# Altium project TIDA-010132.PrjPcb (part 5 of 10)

## Sheet CLOCK MAIN SHEET.SchDoc
size 558 x 431 mm; Date: Not shown in title block; ApprovedBy: Not shown in title block; CheckedBy: Not shown in title block; Author: Not shown in title block; CompanyName: Not shown in title block; DrawnBy: Avinash N; Engineer: Not shown in title block; Organization: Not shown in title block; Address1: Not shown in title block; Address2: Not shown in title block; Address3: Not shown in title block; Address4: Not shown in title block; DocumentNumber: 1; Revision: Use project parameter SCH_Rev; SheetNumber: 24; SheetTotal: 32; PageSetup: Record=PageOptions¦CenterHorizontal=True¦CenterVertical=True¦PrintScale=1.00¦XCorrection=1.00¦YCorrection=1.00¦PrintKind=0¦BorderSize=5000000¦LeftOffset=0¦BottomOffset=0¦Orientation=2¦PaperLength=1000¦PaperWidth=1000¦Scale=100¦PaperSource=15¦PrintQuality=600¦MediaType=1¦DitherType=10¦PaperKind=Letter¦PrintScaleMode=1
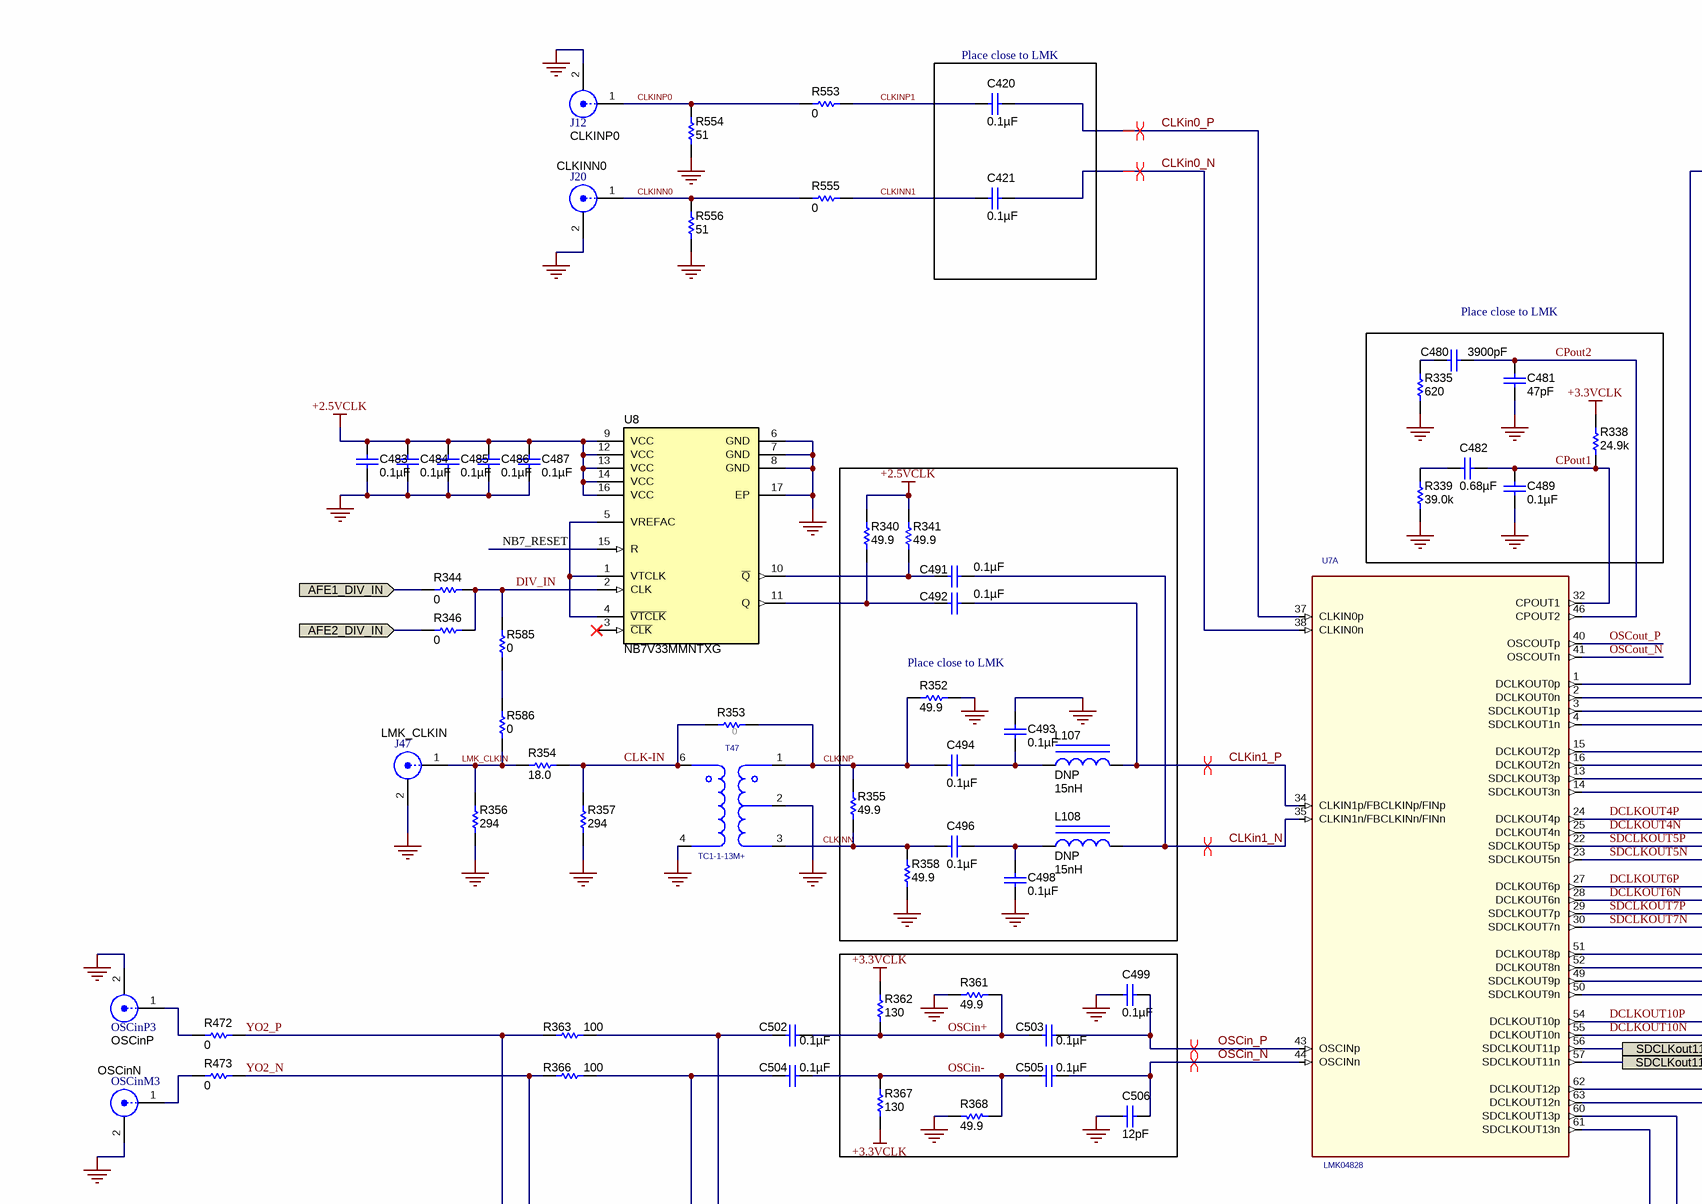
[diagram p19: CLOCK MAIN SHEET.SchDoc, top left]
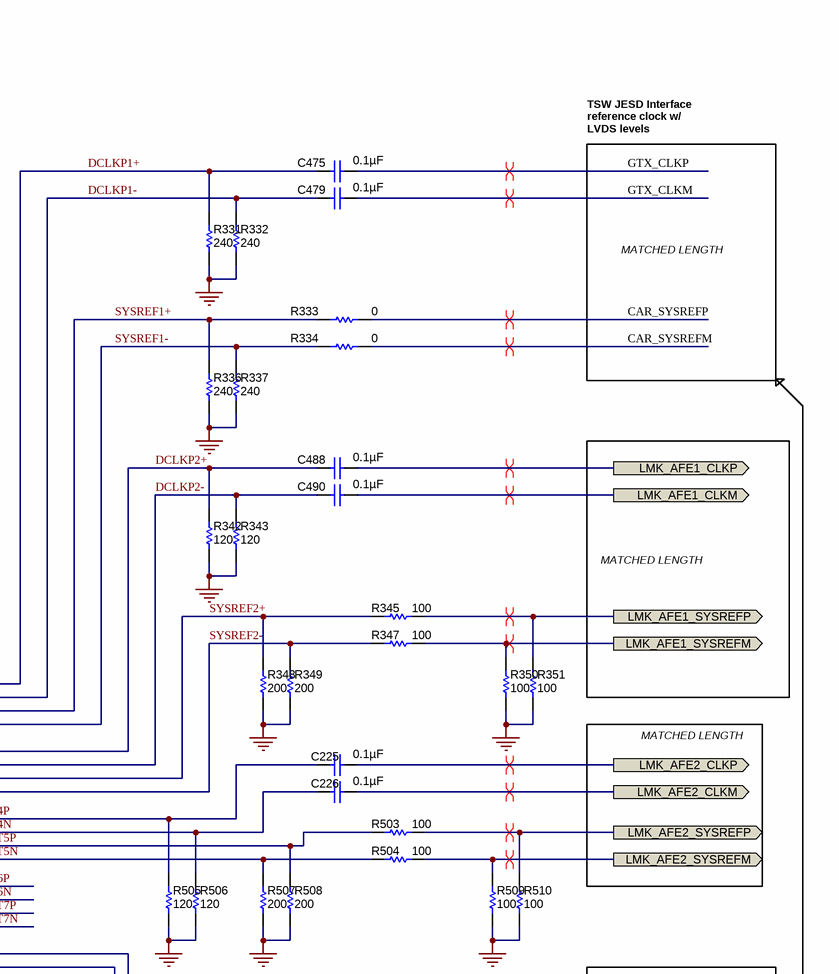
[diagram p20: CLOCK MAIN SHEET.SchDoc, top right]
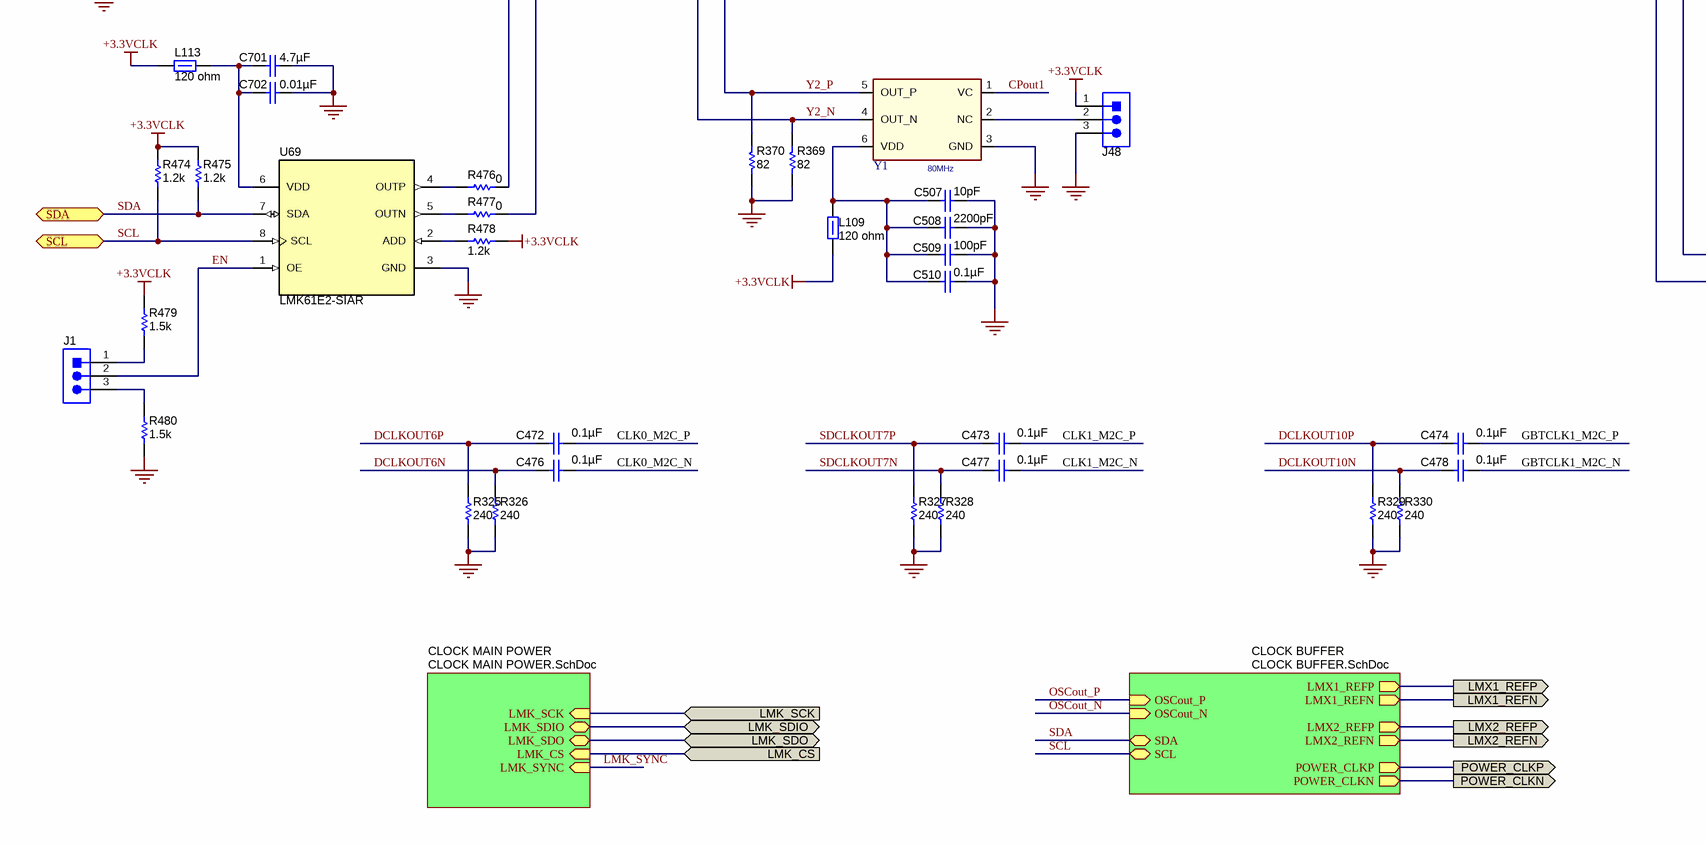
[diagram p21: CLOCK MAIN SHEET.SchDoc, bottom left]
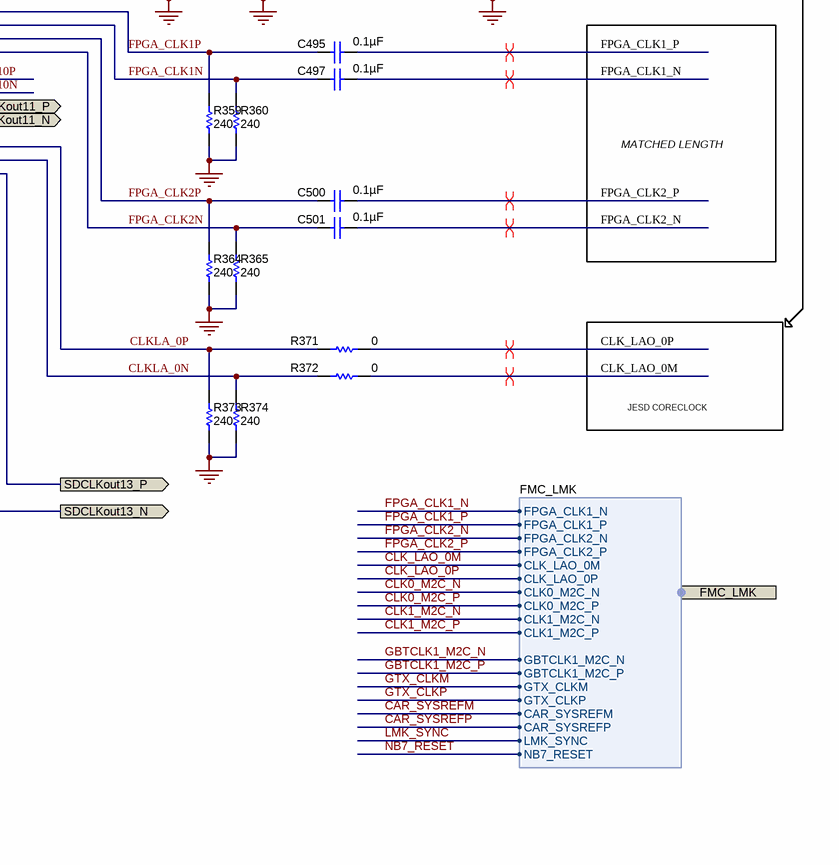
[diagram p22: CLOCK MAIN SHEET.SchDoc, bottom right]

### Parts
C225  ValueDisplayed: 0.1µF  [0402]  (hidden comment: C1005X7R1E104M050BB)
C226  ValueDisplayed: 0.1µF  [0402]  (hidden comment: C1005X7R1E104M050BB)
C420  ValueDisplayed: 0.1µF  [0201_033]  (hidden comment: GRM033R60J104KE19D)
C421  ValueDisplayed: 0.1µF  [0201_033]  (hidden comment: GRM033R60J104KE19D)
C472  ValueDisplayed: 0.1µF  [0402]  (hidden comment: C1005X7R1E104M050BB)
C473  ValueDisplayed: 0.1µF  [0402]  (hidden comment: C1005X7R1E104M050BB)
C474  ValueDisplayed: 0.1µF  [0402]  (hidden comment: C1005X7R1E104M050BB)
C475  ValueDisplayed: 0.1µF  [0402]  (hidden comment: C1005X7R1E104M050BB)
C476  ValueDisplayed: 0.1µF  [0402]  (hidden comment: C1005X7R1E104M050BB)
C477  ValueDisplayed: 0.1µF  [0402]  (hidden comment: C1005X7R1E104M050BB)
C478  ValueDisplayed: 0.1µF  [0402]  (hidden comment: C1005X7R1E104M050BB)
C479  ValueDisplayed: 0.1µF  [0402]  (hidden comment: C1005X7R1E104M050BB)
C480  ValueDisplayed: 3900pF  [0201]  (hidden comment: 0201ZD392KAT2A)
C481  ValueDisplayed: 47pF  [0201_033]  (hidden comment: GRM0335C1E470JA01D)
C482  ValueDisplayed: 0.68µF  [0402]  (hidden comment: C1005X5R1A684K050BB)
C483  ValueDisplayed: 0.1µF  [0402]  (hidden comment: C1005X7R1E104M050BB)
C484  ValueDisplayed: 0.1µF  [0402]  (hidden comment: C1005X7R1E104M050BB)
C485  ValueDisplayed: 0.1µF  [0402]  (hidden comment: C1005X7R1E104M050BB)
C486  ValueDisplayed: 0.1µF  [0402]  (hidden comment: C1005X7R1E104M050BB)
C487  ValueDisplayed: 0.1µF  [0402]  (hidden comment: C1005X7R1E104M050BB)
C488  ValueDisplayed: 0.1µF  [0402]  (hidden comment: C1005X7R1E104M050BB)
C489  ValueDisplayed: 0.1µF  [0402]  (hidden comment: C1005X7R1E104M050BB)
C490  ValueDisplayed: 0.1µF  [0402]  (hidden comment: C1005X7R1E104M050BB)
C491  ValueDisplayed: 0.1µF  [0201_033]  (hidden comment: GRM033R60J104KE19D)
C492  ValueDisplayed: 0.1µF  [0201_033]  (hidden comment: GRM033R60J104KE19D)
C493  ValueDisplayed: 0.1µF  [0201_033]  (hidden comment: GRM033R60J104KE19D)
C494  ValueDisplayed: 0.1µF  [0201_033]  (hidden comment: GRM033R60J104KE19D)
C495  ValueDisplayed: 0.1µF  [0402]  (hidden comment: C1005X7R1E104M050BB)
C496  ValueDisplayed: 0.1µF  [0201_033]  (hidden comment: GRM033R60J104KE19D)
C497  ValueDisplayed: 0.1µF  [0402]  (hidden comment: C1005X7R1E104M050BB)
C498  ValueDisplayed: 0.1µF  [0201_033]  (hidden comment: GRM033R60J104KE19D)
C499  ValueDisplayed: 0.1µF  [0402]  (hidden comment: C1005X7R1E104M050BB)
C500  ValueDisplayed: 0.1µF  [0402]  (hidden comment: C1005X7R1E104M050BB)
C501  ValueDisplayed: 0.1µF  [0402]  (hidden comment: C1005X7R1E104M050BB)
C502  ValueDisplayed: 0.1µF  [0402]  (hidden comment: C1005X7R1E104M050BB)
C503  ValueDisplayed: 0.1µF  [0402]  (hidden comment: C1005X7R1E104M050BB)
C504  ValueDisplayed: 0.1µF  [0402]  (hidden comment: C1005X7R1E104M050BB)
C505  ValueDisplayed: 0.1µF  [0402]  (hidden comment: C1005X7R1E104M050BB)
C506  ValueDisplayed: 12pF  [0402]  (hidden comment: C0402C120J3GACAUTO)
C507  ValueDisplayed: 10pF  [0402]  (hidden comment: GRM1555C1H100JA01D)
C508  ValueDisplayed: 2200pF  [0402]  (hidden comment: GRM155R71E222KA01D)
C509  ValueDisplayed: 100pF  [0402]  (hidden comment: 04025A101FAT2A)
C510  ValueDisplayed: 0.1µF  [0402]  (hidden comment: C1005X7R1E104M050BB)
C701  ValueDisplayed: 4.7µF  [0402]  (hidden comment: C1005X5R0J475M050BC)
C702  ValueDisplayed: 0.01µF  [0402]  (hidden comment: GRM155R71E103KA01D)
J1  800-10-003-10-001000  [Mill-Max_800-10-003-10-001000]  (value not drawn)
J12  CLKINP0  [Molex_0853050232]
J20  CLKINN0  [Molex_0853050232]
J47  LMK_CLKIN  [Molex_0853050232]
J48  0022284033  [Molex_0022284033]  (value not drawn)
L107  DNP  ValueDisplayed: 15nH  [IND_LQG15H]
L108  DNP  ValueDisplayed: 15nH  [IND_LQG15H]
L109  ValueDisplayed: 120 ohm  [0603]  (hidden comment: BLM18SG121TN1D)
L113  ValueDisplayed: 120 ohm  [0603]  (hidden comment: BLM18SG121TN1D)
OSCinM3  OSCinN  [Molex_0853050232]
OSCinP3  OSCinP  [Molex_0853050232]
R325  ValueDisplayed: 240  [0402]  (hidden comment: ERJ-2RKF2400X)
R326  ValueDisplayed: 240  [0402]  (hidden comment: ERJ-2RKF2400X)
R327  ValueDisplayed: 240  [0402]  (hidden comment: ERJ-2RKF2400X)
R328  ValueDisplayed: 240  [0402]  (hidden comment: ERJ-2RKF2400X)
R329  ValueDisplayed: 240  [0402]  (hidden comment: ERJ-2RKF2400X)
R330  ValueDisplayed: 240  [0402]  (hidden comment: ERJ-2RKF2400X)
R331  ValueDisplayed: 240  [0402]  (hidden comment: ERJ-2RKF2400X)
R332  ValueDisplayed: 240  [0402]  (hidden comment: ERJ-2RKF2400X)
R333  ValueDisplayed: 0  [0402]  (hidden comment: ERJ-2GE0R00X)
R334  ValueDisplayed: 0  [0402]  (hidden comment: ERJ-2GE0R00X)
R335  ValueDisplayed: 620  [0201]  (hidden comment: RC0201FR-07620RL)
R336  ValueDisplayed: 240  [0402]  (hidden comment: ERJ-2RKF2400X)
R337  ValueDisplayed: 240  [0402]  (hidden comment: ERJ-2RKF2400X)
R338  ValueDisplayed: 24.9k  [0603]  (hidden comment: CRCW060324K9FKEA)
R339  ValueDisplayed: 39.0k  [0201]  (hidden comment: RC0201FR-0739KL)
R340  ValueDisplayed: 49.9  [0201]  (hidden comment: CRCW020149R9FKED)
R341  ValueDisplayed: 49.9  [0201]  (hidden comment: CRCW020149R9FKED)
R342  ValueDisplayed: 120  [0402]  (hidden comment: CRCW0402120RJNED)
R343  ValueDisplayed: 120  [0402]  (hidden comment: CRCW0402120RJNED)
R344  ValueDisplayed: 0  [0402]  (hidden comment: CRCW04020000Z0ED)
R345  ValueDisplayed: 100  [0402]  (hidden comment: ERJ-2RKF1000X)
R346  ValueDisplayed: 0  [0402]  (hidden comment: CRCW04020000Z0ED)
R347  ValueDisplayed: 100  [0402]  (hidden comment: ERJ-2RKF1000X)
R348  ValueDisplayed: 200  [0402]  (hidden comment: CRCW0402200RJNED)
R349  ValueDisplayed: 200  [0402]  (hidden comment: CRCW0402200RJNED)
R350  ValueDisplayed: 100  [0402]  (hidden comment: ERJ-2RKF1000X)
R351  ValueDisplayed: 100  [0402]  (hidden comment: ERJ-2RKF1000X)
R352  ValueDisplayed: 49.9  [0201]  (hidden comment: CRCW020149R9FKED)
R353  ValueDisplayed: 0  [0603]  (hidden comment: CRCW06030000Z0EA)
R354  ValueDisplayed: 18.0  [0603]  (hidden comment: RC0603FR-0718RL)
R355  ValueDisplayed: 49.9  [0201]  (hidden comment: CRCW020149R9FKED)
R356  ValueDisplayed: 294  [0603]  (hidden comment: CRCW0603294RFKEA)
R357  ValueDisplayed: 294  [0603]  (hidden comment: CRCW0603294RFKEA)
R358  ValueDisplayed: 49.9  [0201]  (hidden comment: CRCW020149R9FKED)
R359  ValueDisplayed: 240  [0402]  (hidden comment: ERJ-2RKF2400X)
R360  ValueDisplayed: 240  [0402]  (hidden comment: ERJ-2RKF2400X)
R361  ValueDisplayed: 49.9  [0402]  (hidden comment: CRCW040249R9FKED)
R362  ValueDisplayed: 130  [0402]  (hidden comment: CRCW0402130RFKED)
R363  ValueDisplayed: 100  [0402]  (hidden comment: ERJ-2RKF1000X)
R364  ValueDisplayed: 240  [0402]  (hidden comment: ERJ-2RKF2400X)
R365  ValueDisplayed: 240  [0402]  (hidden comment: ERJ-2RKF2400X)
R366  ValueDisplayed: 100  [0402]  (hidden comment: ERJ-2RKF1000X)
R367  ValueDisplayed: 130  [0402]  (hidden comment: CRCW0402130RFKED)
R368  ValueDisplayed: 49.9  [0402]  (hidden comment: CRCW040249R9FKED)
R369  ValueDisplayed: 82  [0402]  (hidden comment: CRCW040282R0JNED)
R370  ValueDisplayed: 82  [0402]  (hidden comment: CRCW040282R0JNED)
R371  ValueDisplayed: 0  [0402]  (hidden comment: ERJ-2GE0R00X)
R372  ValueDisplayed: 0  [0402]  (hidden comment: ERJ-2GE0R00X)
R373  ValueDisplayed: 240  [0402]  (hidden comment: ERJ-2RKF2400X)
R374  ValueDisplayed: 240  [0402]  (hidden comment: ERJ-2RKF2400X)
R472  ValueDisplayed: 0  [0402]  (hidden comment: CRCW04020000Z0ED)
R473  ValueDisplayed: 0  [0402]  (hidden comment: CRCW04020000Z0ED)
R474  ValueDisplayed: 1.2k  [0402]  (hidden comment: CRCW04021K20JNED)
R475  ValueDisplayed: 1.2k  [0402]  (hidden comment: CRCW04021K20JNED)
R476  ValueDisplayed: 0  [0402]  (hidden comment: CRCW04020000Z0ED)
R477  ValueDisplayed: 0  [0402]  (hidden comment: CRCW04020000Z0ED)
R478  ValueDisplayed: 1.2k  [0402]  (hidden comment: CRCW04021K20JNED)
R479  ValueDisplayed: 1.5k  [0402]  (hidden comment: CRCW04021K50JNED)
R480  ValueDisplayed: 1.5k  [0402]  (hidden comment: CRCW04021K50JNED)
R503  ValueDisplayed: 100  [0402]  (hidden comment: ERJ-2RKF1000X)
R504  ValueDisplayed: 100  [0402]  (hidden comment: ERJ-2RKF1000X)
R505  ValueDisplayed: 120  [0402]  (hidden comment: CRCW0402120RJNED)
R506  ValueDisplayed: 120  [0402]  (hidden comment: CRCW0402120RJNED)
R507  ValueDisplayed: 200  [0402]  (hidden comment: CRCW0402200RJNED)
R508  ValueDisplayed: 200  [0402]  (hidden comment: CRCW0402200RJNED)
R509  ValueDisplayed: 100  [0402]  (hidden comment: ERJ-2RKF1000X)
R510  ValueDisplayed: 100  [0402]  (hidden comment: ERJ-2RKF1000X)
R553  ValueDisplayed: 0  [0201]  (hidden comment: CRCW02010000Z0ED)
R554  ValueDisplayed: 51  [0201]  (hidden comment: RC0201JR-0751RL)
R555  ValueDisplayed: 0  [0201]  (hidden comment: CRCW02010000Z0ED)
R556  ValueDisplayed: 51  [0201]  (hidden comment: RC0201JR-0751RL)
R585  ValueDisplayed: 0  [0402]  (hidden comment: CRCW04020000Z0ED)
R586  ValueDisplayed: 0  [0402]  (hidden comment: CRCW04020000Z0ED)
T47  TC1-1-13M+  [TFMR_5_150x150_50]
U7  LMK04828  [NKD0064A]  (part A of 2)
U8  NB7V33MMNTXG  [QFN16-3x3MM_0_5]
U69  LMK61E2-SIAR  [SIA0008B]
Y1  80MHz  [VCXO_6_CUSTOM]

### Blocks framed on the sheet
Place close to LMK: C420 C421
Place close to LMK: C480-C482 C489 R335 R338 R339
Place close to LMK: C491-C494 C496 C498 L107 L108 R340 R341 R352 R355 R358

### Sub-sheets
CLOCK BUFFER = CLOCK BUFFER.SchDoc: POWER_CLKP (out), LMX2_REFP (out), POWER_CLKN (out), LMX1_REFP (out), SCL (bidir), SDA (bidir), OSCout_N (in), OSCout_P (in), LMX1_REFN (out), LMX2_REFN (out)
CLOCK MAIN POWER = CLOCK MAIN POWER.SchDoc: LMK_SYNC (in), LMK_SDO (bidir), LMK_CS (in), LMK_SCK (in), LMK_SDIO (bidir)

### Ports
AFE1_DIV_IN (in), AFE2_DIV_IN (in), FMC_LMK (harness FMC_LMK), LMK_AFE1_CLKM (out), LMK_AFE1_CLKP (out), LMK_AFE1_SYSREFM (out), LMK_AFE1_SYSREFP (out), LMK_AFE2_CLKM (out), LMK_AFE2_CLKP (out), LMK_AFE2_SYSREFM (out), LMK_AFE2_SYSREFP (out), LMK_CS (in), LMK_SCK (in), LMK_SDIO (bidir), LMK_SDO (bidir), LMX1_REFN (out), LMX1_REFP (out), LMX2_REFN (out), LMX2_REFP (out), POWER_CLKN (out), POWER_CLKP (out), SCL (bidir), SDA (bidir), SDCLKout11_N (out), SDCLKout11_P (out), SDCLKout13_N (out), SDCLKout13_P (out)

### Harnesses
FMC_LMK: FPGA_CLK1_N, FPGA_CLK1_P, FPGA_CLK2_N, FPGA_CLK2_P, GBTCLK1_M2C_N, GBTCLK1_M2C_P, GTX_CLKM, GTX_CLKP, CAR_SYSREFM, CAR_SYSREFP, LMK_SYNC, NB7_RESET, CLK_LAO_0M, CLK_LAO_0P, CLK0_M2C_N, CLK0_M2C_P, CLK1_M2C_N, CLK1_M2C_P

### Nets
+2.5VCLK: C483.2 C484.2 C485.2 C486.2 C487.2 R340.2 R341.2 U8.9(VCC) U8.12(VCC) U8.13(VCC) U8.14(VCC) U8.16(VCC)
+3.3VCLK: J48.1 L109.2 L113.1 R338.2 R362.1 R367.1 R474.2 R475.2 R478.1 R479.2
GND: C481.2 C483.1 C484.1 C485.1 C486.1 C487.1 C489.1 C493.1 C498.1 C499.1 C506.1 C507.1 C508.1 C509.1 C510.1 C701.1 C702.1 J12.2 J20.2 J47.2 J48.3 OSCinM3.2 OSCinP3.2 R325.1 R326.1 R327.1 R328.1 R329.1 R330.1 R331.1 R332.1 R335.1 R336.1 R337.1 R339.1 R342.1 R343.1 R348.1 R349.1 R350.1 R351.1 R352.2 R356.1 R357.1 R358.1 R359.1 R360.1 R361.1 R364.1 R365.1 R368.1 R369.1 R370.1 R373.1 R374.1 R480.1 R505.1 R506.1 R507.1 R508.1 R509.1 R510.1 R554.1 R556.1 T47.2(secondary_ct) T47.4(primary) U8.6(GND) U8.7(GND) U8.8(GND) U8.17(EP) U69.3(GND) Y1.3(GND)
AFE1_DIV_IN: R344.2 ; port AFE1_DIV_IN
AFE2_DIV_IN: R346.2 ; port AFE2_DIV_IN
CAR_SYSREFM: R334.2 ; port FMC_LMK.CAR_SYSREFM
CAR_SYSREFP: R333.2 ; port FMC_LMK.CAR_SYSREFP
CLK0_M2C_N: C476.2 ; port FMC_LMK.CLK0_M2C_N
CLK0_M2C_P: C472.2 ; port FMC_LMK.CLK0_M2C_P
CLK1_M2C_N: C477.2 ; port FMC_LMK.CLK1_M2C_N
CLK1_M2C_P: C473.2 ; port FMC_LMK.CLK1_M2C_P
CLK-IN: R353.1 R354.2 R357.2 T47.6(primary_dot)
CLK_LAO_0M: R372.2 ; port FMC_LMK.CLK_LAO_0M
CLK_LAO_0P: R371.2 ; port FMC_LMK.CLK_LAO_0P
CLKin0_N: C421.2 U7.38(CLKIN0n)
CLKin0_P: C420.2 U7.37(CLKIN0p)
CLKin1_N: C491.2 L108.2 U7.35(CLKIN1n/FBCLKINn/FINn)
CLKin1_P: C492.2 L107.2 U7.34(CLKIN1p/FBCLKINp/FINp)
CLKINN: C496.1 R355.1 R358.2 T47.3(secondary)
CLKINN0: J20.1 R555.1 R556.2
CLKINN1: C421.1 R555.2
CLKINP: C494.1 R352.1 R353.2 R355.2 T47.1(secondary_dot)
CLKINP0: J12.1 R553.1 R554.2
CLKINP1: C420.1 R553.2
CLKLA_0N: R372.1 R374.2 U7.63(DCLKOUT12n)
CLKLA_0P: R371.1 R373.2 U7.62(DCLKOUT12p)
CPout1: C482.2 C489.2 R338.1 U7.32(CPOUT1) Y1.1(VC)
CPout2: C480.1 C481.1 U7.46(CPOUT2)
DCLKOUT4N: C226.1 R506.2 U7.25(DCLKOUT4n)
DCLKOUT4P: C225.1 R505.2 U7.24(DCLKOUT4p)
DCLKOUT6N: C476.1 R326.2 U7.28(DCLKOUT6n)
DCLKOUT6P: C472.1 R325.2 U7.27(DCLKOUT6p)
DCLKOUT10N: C478.1 R330.2 U7.55(DCLKOUT10n)
DCLKOUT10P: C474.1 R329.2 U7.54(DCLKOUT10p)
DCLKP1+: C475.1 R331.2 U7.1(DCLKOUT0p)
DCLKP1-: C479.1 R332.2 U7.2(DCLKOUT0n)
DCLKP2+: C488.1 R342.2 U7.15(DCLKOUT2p)
DCLKP2-: C490.1 R343.2 U7.16(DCLKOUT2n)
DIV_IN: R344.1 R346.1 R585.1 U8.2(CLK)
EN: J1.2 U69.1(OE)
FPGA_CLK1_N: C497.2 ; port FMC_LMK.FPGA_CLK1_N
FPGA_CLK1_P: C495.2 ; port FMC_LMK.FPGA_CLK1_P
FPGA_CLK1N: C497.1 R360.2 U7.52(DCLKOUT8n)
FPGA_CLK1P: C495.1 R359.2 U7.51(DCLKOUT8p)
FPGA_CLK2_N: C501.2 ; port FMC_LMK.FPGA_CLK2_N
FPGA_CLK2_P: C500.2 ; port FMC_LMK.FPGA_CLK2_P
FPGA_CLK2N: C501.1 R365.2 U7.50(SDCLKOUT9n)
FPGA_CLK2P: C500.1 R364.2 U7.49(SDCLKOUT9p)
GBTCLK1_M2C_N: C478.2 ; port FMC_LMK.GBTCLK1_M2C_N
GBTCLK1_M2C_P: C474.2 ; port FMC_LMK.GBTCLK1_M2C_P
GTX_CLKM: C479.2 ; port FMC_LMK.GTX_CLKM
GTX_CLKP: C475.2 ; port FMC_LMK.GTX_CLKP
LMK_AFE1_CLKM: C490.2 ; port LMK_AFE1_CLKM
LMK_AFE1_CLKP: C488.2 ; port LMK_AFE1_CLKP
LMK_AFE1_SYSREFM: R347.2 R350.2 ; port LMK_AFE1_SYSREFM
LMK_AFE1_SYSREFP: R345.2 R351.2 ; port LMK_AFE1_SYSREFP
LMK_AFE2_CLKM: C226.2 ; port LMK_AFE2_CLKM
LMK_AFE2_CLKP: C225.2 ; port LMK_AFE2_CLKP
LMK_AFE2_SYSREFM: R504.2 R509.2 ; port LMK_AFE2_SYSREFM
LMK_AFE2_SYSREFP: R503.2 R510.2 ; port LMK_AFE2_SYSREFP
LMK_CLKIN: J47.1 R354.1 R356.2 R586.2
LMK_CS: port LMK_CS, sheet CLOCK MAIN POWER/LMK_CS
LMK_SCK: port LMK_SCK, sheet CLOCK MAIN POWER/LMK_SCK
LMK_SDIO: port LMK_SDIO, sheet CLOCK MAIN POWER/LMK_SDIO
LMK_SDO: port LMK_SDO, sheet CLOCK MAIN POWER/LMK_SDO
LMK_SYNC: sheet CLOCK MAIN POWER/LMK_SYNC, port FMC_LMK.LMK_SYNC
LMX1_REFN: port LMX1_REFN, sheet CLOCK BUFFER/LMX1_REFN
LMX1_REFP: port LMX1_REFP, sheet CLOCK BUFFER/LMX1_REFP
LMX2_REFN: port LMX2_REFN, sheet CLOCK BUFFER/LMX2_REFN
LMX2_REFP: port LMX2_REFP, sheet CLOCK BUFFER/LMX2_REFP
NB7_RESET: U8.15(R) ; port FMC_LMK.NB7_RESET
OSCin+: C502.1 C503.2 R361.2 R362.2
OSCin-: C504.1 C505.2 R367.2 R368.2
OSCin_N: C505.1 C506.2 U7.44(OSCINn)
OSCin_P: C499.2 C503.1 U7.43(OSCINp)
OSCout_N: U7.41(OSCOUTn) ; sheet CLOCK BUFFER/OSCout_N
OSCout_P: U7.40(OSCOUTp) ; sheet CLOCK BUFFER/OSCout_P
POWER_CLKN: port POWER_CLKN, sheet CLOCK BUFFER/POWER_CLKN
POWER_CLKP: port POWER_CLKP, sheet CLOCK BUFFER/POWER_CLKP
SCL: R474.1 U69.8(SCL) ; port SCL, sheet CLOCK BUFFER/SCL
SDA: R475.1 U69.7(SDA) ; port SDA, sheet CLOCK BUFFER/SDA
SDCLKOUT5N: R504.1 R507.2 U7.23(SDCLKOUT5n)
SDCLKOUT5P: R503.1 R508.2 U7.22(SDCLKOUT5p)
SDCLKOUT7N: C477.1 R328.2 U7.30(SDCLKOUT7n)
SDCLKOUT7P: C473.1 R327.2 U7.29(SDCLKOUT7p)
SDCLKout11_N: U7.57(SDCLKOUT11n) ; port SDCLKout11_N
SDCLKout11_P: U7.56(SDCLKOUT11p) ; port SDCLKout11_P
SDCLKout13_N: U7.61(SDCLKOUT13n) ; port SDCLKout13_N
SDCLKout13_P: U7.60(SDCLKOUT13p) ; port SDCLKout13_P
SYSREF1+: R333.1 R336.2 U7.3(SDCLKOUT1p)
SYSREF1-: R334.1 R337.2 U7.4(SDCLKOUT1n)
SYSREF2+: R345.1 R348.2 U7.13(SDCLKOUT3p)
SYSREF2-: R347.1 R349.2 U7.14(SDCLKOUT3n)
Y2_N: C504.2 R366.2 R369.2 Y1.4(OUT_N)
Y2_P: C502.2 R363.2 R370.2 Y1.5(OUT_P)
YO2_N: R366.1 R473.1 R477.2
YO2_P: R363.1 R472.1 R476.2
NetC480_2: C480.2 R335.2
NetC482_1: C482.1 R339.2
NetC491_1: C491.1 R341.1 U8.10(~{Q})
NetC492_1: C492.1 R340.1 U8.11(Q)
NetC493_2: C493.2 C494.2 L107.1
NetC496_2: C496.2 C498.2 L108.1
NetC507_2: C507.2 C508.2 C509.2 C510.2 L109.1 Y1.6(VDD)
NetC701_2: C701.2 C702.2 L113.2 U69.6(VDD)
NetJ1_1: J1.1 R479.1
NetJ1_3: J1.3 R480.2
NetJ48_2: J48.2 Y1.2(NC)
NetOSCinM3_1: OSCinM3.1 R473.2
NetOSCinP3_1: OSCinP3.1 R472.2
NetR476_1: R476.1 U69.4(OUTP)
NetR477_1: R477.1 U69.5(OUTN)
NetR478_2: R478.2 U69.2(ADD)
NetR585_2: R585.2 R586.1
NetU8_1: U8.1(VTCLK) U8.4(~{VTCLK}) U8.5(VREFAC)

Not connected (* = marked no-connect by the designer): U8 3(~{CLK})*

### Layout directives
differential pair: CAR_SYSREFM, CAR_SYSREFP, CLK_LAO_0M, CLK_LAO_0P, CLKin0_N, CLKin0_P, CLKin1_N, CLKin1_P, FPGA_CLK1_N, FPGA_CLK1_P, FPGA_CLK2_N, FPGA_CLK2_P, GTX_CLKM, LMK_AFE1_CLKM, LMK_AFE1_CLKP, LMK_AFE1_SYSREFM, LMK_AFE1_SYSREFP, LMK_AFE2_CLKM, LMK_AFE2_CLKP, LMK_AFE2_SYSREFM, LMK_AFE2_SYSREFP, OSCin_N, OSCin_P
differential pair; differential pair class *: GTX_CLKP

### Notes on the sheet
- TSW JESD Interface
  reference clock w/
  LVDS levels
- MATCHED LENGTH
- JESD CORECLOCK

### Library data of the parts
C225 C226 C472-C479 C483-C490 C495 C497 C499-C505 C510 = C1005X7R1E104M050BB: CAP, CERM, 0.1 µF, 25 V, +/- 20%, X7R, 0402; Manufacturer: TDK; Polarized: N; TaMax_C: 125; TaMin_C: -55; Tolerance_%: 20; VDC_V: 25; Cap_F: 0.0000001; CompType: Capacitor; Value: 0.1uF; Value1: Unknown; Value2: 25V; U/M: EA; SizeArea_mm2: 0.5; SizeAreaWB_mm2: 3; SizeX_mm: 1; SizeZ_mm: 0.6; AEC Category: Q200
C420 C421 C491-C494 C496 C498 = GRM033R60J104KE19D: CAP, CERM, 0.1 µF, 6.3 V, +/- 10%, X5R, 0201; Manufacturer: MuRata; Polarized: N; CompType: Capacitor; Value: 0.1uF; U/M: EA; Cap_F: 0.0000001; Tolerance_%: 10; Value1: Unknown; VDC_V: 6.3; Value2: 6.3V; TaMin_C: -55; TaMax_C: 85; Cap_Case: 0201; SizeArea_mm2: 0.18; SizeAreaWB_mm2: 2.08; SizeX_mm: 0.6; SizeY_mm: 0.3; SizeZ_mm: 0.33; AEC Category: Q200
C480 = 0201ZD392KAT2A: CAP, CERM, 3900 pF, 10 V, +/- 10%, X5R, 0201; Manufacturer: AVX; Polarized: N; CompType: Capacitor; Value: 3900pF; U/M: EA; Cap_F: 0.0000000039; Tolerance_%: 10; Value1: Unknown; Value2: 10V; TaMin_C: -55; TaMax_C: 85; SizeArea_mm2: 0.18; SizeAreaWB_mm2: 2.08; SizeX_mm: 0.6; SizeY_mm: 0.3; SizeZ_mm: 0.26; AEC Category: Q200
C481 = GRM0335C1E470JA01D: CAP, CERM, 47 pF, 25 V, +/- 5%, C0G/NP0, 0201; Manufacturer: MuRata; Polarized: N; CompType: Capacitor; Value: 47pF; U/M: EA; Cap_F: 0.000000000047; Tolerance_%: 5; Value1: Unknown; VDC_V: 25; Value2: 25V; TaMin_C: -55; TaMax_C: 125; Cap_Case: 0201; SizeArea_mm2: 0.18; SizeAreaWB_mm2: 2.08; SizeX_mm: 0.6; SizeY_mm: 0.3; SizeZ_mm: 0.33; AEC Category: Q200
C482 = C1005X5R1A684K050BB: CAP, CERM, 0.68 µF, 10 V, +/- 10%, X5R, 0402; Manufacturer: TDK; Polarized: N; CompType: Capacitor; Value: 0.68uF; U/M: EA; Cap_F: 0.00000068; Tolerance_%: 10; Value1: Unknown; Value2: 10V; TaMin_C: -55; TaMax_C: 85; SizeArea_mm2: 0.5; SizeAreaWB_mm2: 3; SizeX_mm: 1; SizeZ_mm: 0.6; AEC Category: Q200
C506 = C0402C120J3GACAUTO: CAP, CERM, 12 pF, 25 V, +/- 5%, C0G/NP0, AEC-Q200 Grade 1, 0402; Manufacturer: Kemet; Polarized: N; CompType: Capacitor; Value: 12pF; U/M: EA; Cap_F: 0.000000000012; Tolerance_%: 5; Value1: Unknown; VDC_V: 25; Value2: 25V; TaMin_C: -55; TaMax_C: 125; SizeArea_mm2: 0.5; SizeAreaWB_mm2: 3; SizeX_mm: 1; SizeZ_mm: 0.6; AEC Category: Q200; AEC Qualified: Y
C507 = GRM1555C1H100JA01D: CAP, CERM, 10 pF, 50 V, +/- 5%, C0G/NP0, 0402; Manufacturer: MuRata; Polarized: N; CompType: Capacitor; Value: 10pF; U/M: EA; Cap_F: 0.00000000001; Tolerance_%: 5; Value1: Unknown; VDC_V: 50; Value2: 50V; TaMin_C: -55; TaMax_C: 125; SizeArea_mm2: 0.5; SizeAreaWB_mm2: 3; SizeX_mm: 1; SizeZ_mm: 0.6; AEC Category: Q200
C508 = GRM155R71E222KA01D: CAP, CERM, 2200 pF, 25 V, +/- 10%, X7R, 0402; Manufacturer: MuRata; Polarized: N; CompType: Capacitor; Value: 2200pF; U/M: EA; Cap_F: 0.0000000022; Tolerance_%: 10; Value1: Unknown; VDC_V: 25; Value2: 25V; TaMin_C: -55; TaMax_C: 125; SizeArea_mm2: 0.5; SizeAreaWB_mm2: 3; SizeX_mm: 1; SizeZ_mm: 0.6; AEC Category: Q200
C509 = 04025A101FAT2A: CAP, CERM, 100 pF, 50 V, +/- 1%, C0G/NP0, 0402; Manufacturer: AVX; Polarized: N; CompType: Capacitor; Value: 100pF; U/M: EA; Cap_F: 0.0000000001; Tolerance_%: 1; Value1: Unknown; VDC_V: 50; Value2: 50V; TaMin_C: -55; TaMax_C: 125; SizeArea_mm2: 0.5; SizeAreaWB_mm2: 3; SizeZ_mm: 0.6; AEC Category: Q200
C701 = C1005X5R0J475M050BC: CAP, CERM, 4.7 µF, 6.3 V, +/- 20%, X5R, 0402; Manufacturer: TDK; Polarized: N; CompType: Capacitor; Value: 4.7uF; U/M: EA; Cap_F: 0.0000047; Tolerance_%: 20; Value1: Unknown; VDC_V: 6.3; Value2: 6.3V; TaMin_C: -55; TaMax_C: 85; SizeArea_mm2: 0.5; SizeAreaWB_mm2: 3; SizeX_mm: 1; SizeZ_mm: 0.6; AEC Category: Q200
C702 = GRM155R71E103KA01D: CAP, CERM, 0.01 µF, 25 V, +/- 10%, X7R, 0402; Manufacturer: MuRata; Polarized: N; CompType: Capacitor; Value: 0.01uF; U/M: EA; Cap_F: 0.00000001; Tolerance_%: 10; Value1: Unknown; VDC_V: 25; Value2: 25V; TaMin_C: -55; TaMax_C: 125; SizeArea_mm2: 0.5; SizeAreaWB_mm2: 3; SizeX_mm: 1; SizeZ_mm: 0.6; AEC Category: Q200
J1 = 800-10-003-10-001000: Header, 100mil, 3x1, TH; Manufacturer: Mill-Max; SymbolCreator: a0799628
J12 J20 J47 OSCinM3 OSCinP3 = CMP-0077224-1: Plug, 50 Ohm, Straight, SMT; PartNumber: 0853050232; Manufacturer: Molex; Cert_UL: Y; ContactFinish: Gold; CT: False; Gender: Male; Voltage_V: 335V
J48 = 0022284033: Header, 2.54mm, 3x1, Tin, TH; Manufacturer: Molex; SymbolCreator: a0799628; Pitch_mm: 2.54; Gender: Male; Shrouded: N; Row_Count: 1; Current_A: 4; Voltage_V: 250; Cert_UL: Y
L107 L108 = LQG15HS15NJ02D: Inductor, Multilayer, Air Core, 15 nH, 0.3 A, 0.32 ohm, SMD; Manufacturer: MuRata; Value: 15nH; Ind_H: 15.0E-9; Imax_A: 0.3; Irms: 0.3A @ C rise; Isat: 0.3A @ % inductance drop; DCR_ohm: 0.32; Value2: 0.3A; SizeAreaWB_mm2: 3; SizeArea_mm2: 0.5; SizeX_mm: 1; SizeZ_mm: 0.55; AEC Category: Q200; Green_Lifecycle: Active; Green_REACh: Passed
L109 L113 = BLM18SG121TN1D: Ferrite Bead, 120 ohm @ 100 MHz, 3 A, 0603; Manufacturer: MuRata; Value: 120 ohm; Imax_A: 3; DCR_ohm: 0.025; Value1: 0.025 ohm; Value2: 3A; SizeAreaWB_mm2: 4.68; SizeArea_mm2: 1.28; SizeX_mm: 1.6; SizeY_mm: 0.8; SizeZ_mm: 1; ZTyp@100MHz_Ohm: 120
R325-R332 R336 R337 R359 R360 R364 R365 R373 R374 = ERJ-2RKF2400X: RES, 240, 1%, 0.1 W, AEC-Q200 Grade 0, 0402; Manufacturer: Panasonic; CompType: Resistor; Value: 240; Value_Code: 240R; Tolerance_%: 1; Power_W: 0.1; Value2: 0.1W; VDC_V: 50; TempCo: 100 ppm/C; SizeArea_mm2: 0.5; SizeZ_mm: 0.6; U/M: EA; AEC Category: Q200; AEC Qualified: Y; AEC Grade: 0; Green_Lifecycle: Active; Green_REACh: Passed
R333 R334 R371 R372 = ERJ-2GE0R00X: RES, 0, 5%, 0.063 W, 0402; Manufacturer: Panasonic; CompType: Resistor; Value: 0; Value_Code: 0000; Tolerance_%: 5; Power_W: 0.063; Value2: 0.063W; VDC_V: 50; TempCo: 600 ppm/C; SizeArea_mm2: 0.5; SizeX_mm: 1; SizeZ_mm: 0.6; EIA_Code: E24; U/M: EA; AEC Category: Q200; Green_Lifecycle: Active; Green_REACh: Passed
R335 = RC0201FR-07620RL: RES, 620, 1%, 0.05 W, 0201; Manufacturer: Yageo America; CompType: Resistor; Value: 620; Value_Code: 620R; Tolerance_%: 1; Power_W: 0.05; Value2: 0.05W; VDC_V: 25; TempCo: 200 ppm/C; SizeArea_mm2: 0.18; SizeX_mm: 0.6; SizeY_mm: 0.3; SizeZ_mm: 0.26; U/M: EA; AEC Category: Q200; AEC Qualified: N
R338 = CRCW060324K9FKEA: RES, 24.9 k, 1%, 0.1 W, 0603; Manufacturer: Vishay-Dale; CompType: Resistor; Value: 24.9k; Res_ohm: 24900; Value_Code: 24k9; Tolerance_%: 1; Power_W: 0.1; Value2: 0.1W; VDC_V: 75; TempCo: 100 ppm/C; SizeArea_mm2: 1.28; SizeX_mm: 1.6; SizeY_mm: 0.8; EIA_Code: E96; U/M: EA; AEC Category: Q200; Green_Lifecycle: Active; Green_REACh: Passed
R339 = RC0201FR-0739KL: RES, 39.0 k, 1%, 0.05 W, 0201; Manufacturer: Yageo America; CompType: Resistor; Value: 39.0k; Res_ohm: 39000; Value_Code: 39k0; Tolerance_%: 1; Power_W: 0.05; Value2: 0.05W; VDC_V: 25; TempCo: 200 ppm/C; SizeArea_mm2: 0.18; SizeX_mm: 0.6; SizeY_mm: 0.3; SizeZ_mm: 0.26; U/M: EA; AEC Category: Q200; AEC Qualified: N
R340 R341 R352 R355 R358 = CRCW020149R9FKED: RES, 49.9, 1%, 0.05 W, 0201; Manufacturer: Vishay-Dale; CompType: Resistor; Value: 49.9; Value_Code: 49R9; Tolerance_%: 1; Power_W: 0.05; Value2: 0.05W; VDC_V: 30; TempCo: 100 ppm/C; SizeArea_mm2: 0.18; SizeX_mm: 0.6; SizeY_mm: 0.3; SizeZ_mm: 0.26; EIA_Code: E96; U/M: EA; AEC Category: Q200; AEC Qualified: N
R342 R343 R505 R506 = CRCW0402120RJNED: RES, 120, 5%, 0.063 W, 0402; Manufacturer: Vishay-Dale; CompType: Resistor; Value: 120; Value_Code: 120R; Tolerance_%: 5; Power_W: 0.063; Value2: 0.063W; VDC_V: 50; TempCo: 200 ppm/C; SizeArea_mm2: 0.5; SizeX_mm: 1; SizeZ_mm: 0.6; EIA_Code: E24; U/M: EA; AEC Category: Q200
R344 R346 R585 R586 = CRCW04020000Z0ED: RES, 0, 5%, 0.063 W, 0402; Manufacturer: Vishay-Dale; CompType: Resistor; Tolerance_%: 5; VDC_V: 50; Power_W: 0.063; Value: 0; U/M: EA; Value_Code: 0000; Value2: 0.063W; EIA_Code: E24; TempCo: 200 ppm/C; SizeArea_mm2: 0.5; SizeX_mm: 1; SizeZ_mm: 0.6; AEC Category: Q200
R345 R347 R350 R351 R363 R366 R503 R504 R509 R510 = ERJ-2RKF1000X: RES, 100, 1%, 0.1 W, 0402; Manufacturer: Panasonic; CompType: Resistor; Value: 100; Value_Code: 100R; Tolerance_%: 1; Power_W: 0.1; Value2: 0.1W; VDC_V: 50; TempCo: 100 ppm/C; SizeArea_mm2: 0.5; SizeZ_mm: 0.6; EIA_Code: E96; U/M: EA; AEC Category: Q200; Green_Lifecycle: Active; Green_REACh: Passed
R348 R349 R507 R508 = CRCW0402200RJNED: RES, 200, 5%, 0.063 W, 0402; Manufacturer: Vishay-Dale; CompType: Resistor; Value: 200; Value_Code: 200R; Tolerance_%: 5; Power_W: 0.063; Value2: 0.063W; VDC_V: 50; TempCo: 200 ppm/C; SizeArea_mm2: 0.5; SizeX_mm: 1; SizeZ_mm: 0.6; EIA_Code: E24; U/M: EA; AEC Category: Q200; Green_Lifecycle: Active; Green_REACh: Passed
R353 = CRCW06030000Z0EA: RES, 0, 5%, 0.1 W, 0603; Manufacturer: Vishay-Dale; CompType: Resistor; Tolerance_%: 5; VDC_V: 75; Power_W: 0.1; Value: 0; U/M: EA; Value_Code: 0000; Value2: 0.1W; EIA_Code: E24; TempCo: 200 ppm/C; SizeArea_mm2: 1.28; SizeX_mm: 1.6; SizeY_mm: 0.8; SizeZ_mm: 1; AEC Category: Q200
R354 = RC0603FR-0718RL: RES, 18.0, 1%, 0.1 W, 0603; Manufacturer: Yageo America; CompType: Resistor; Value: 18.0; Res_ohm: 18; Value_Code: 18R0; Tolerance_%: 1; Power_W: 0.1; Value2: 0.1W; VDC_V: 150; TempCo: 200 ppm/C; SizeArea_mm2: 1.28; SizeX_mm: 1.6; SizeY_mm: 0.8; U/M: EA; AEC Category: Q200
R356 R357 = CRCW0603294RFKEA: RES, 294, 1%, 0.1 W, 0603; Manufacturer: Vishay-Dale; CompType: Resistor; Value: 294; Value_Code: 294R; Tolerance_%: 1; Power_W: 0.1; Value2: 0.1W; VDC_V: 75; TempCo: 100 ppm/C; SizeArea_mm2: 1.28; SizeX_mm: 1.6; SizeY_mm: 0.8; EIA_Code: E96; U/M: EA; AEC Category: Q200
R361 R368 = CRCW040249R9FKED: RES, 49.9, 1%, 0.063 W, 0402; Manufacturer: Vishay-Dale; CompType: Resistor; Value: 49.9; Value_Code: 49R9; Tolerance_%: 1; Power_W: 0.063; Value2: 0.063W; VDC_V: 50; TempCo: 100 ppm/C; EIA_Code: E96; U/M: EA; AEC Category: Q200
R362 R367 = CRCW0402130RFKED: RES, 130, 1%, 0.063 W, 0402; Manufacturer: Vishay-Dale; CompType: Resistor; Value: 130; Value_Code: 130R; Tolerance_%: 1; Power_W: 0.063; Value2: 0.063W; VDC_V: 50; TempCo: 100 ppm/C; SizeArea_mm2: 0.5; SizeZ_mm: 0.6; EIA_Code: E96; U/M: EA; AEC Category: Q200
R369 R370 = CRCW040282R0JNED: RES, 82, 5%, 0.063 W, 0402; Manufacturer: Vishay-Dale; CompType: Resistor; Value: 82; Value_Code: 82R0; Tolerance_%: 5; Power_W: 0.063; Value2: 0.063W; VDC_V: 50; TempCo: 200 ppm/C; SizeArea_mm2: 0.5; SizeX_mm: 1; SizeZ_mm: 0.6; EIA_Code: E24; U/M: EA; AEC Category: Q200
R472 R473 R476 R477 = CRCW04020000Z0ED: RES, 0, 5%, 0.063 W, 0402; Manufacturer: Vishay-Dale; CompType: Resistor; Value: 0; Value_Code: 0000; Tolerance_%: 5; Power_W: 0.063; Value2: 0.063W; VDC_V: 50; TempCo: 200 ppm/C; EIA_Code: E24; U/M: EA; AEC Category: Q200
R474 R475 R478 = CRCW04021K20JNED: RES, 1.2 k, 5%, 0.063 W, 0402; Manufacturer: Vishay-Dale; CompType: Resistor; Value: 1.2k; Res_ohm: 1200; Value_Code: 1k20; Tolerance_%: 5; Power_W: 0.063; Value2: 0.063W; VDC_V: 50; TempCo: 200 ppm/C; EIA_Code: E24; U/M: EA; AEC Category: Q200; SizeArea_mm2: 0.5; SizeX_mm: 1; SizeZ_mm: 0.6
R479 R480 = CRCW04021K50JNED: RES, 1.5 k, 5%, 0.063 W, 0402; Manufacturer: Vishay-Dale; CompType: Resistor; Value: 1.5k; Res_ohm: 1500; Value_Code: 1k50; Tolerance_%: 5; Power_W: 0.063; Value2: 0.063W; VDC_V: 50; TempCo: 200 ppm/C; SizeArea_mm2: 0.5; SizeX_mm: 1; SizeZ_mm: 0.6; EIA_Code: E24; U/M: EA; AEC Category: Q200
R553 R555 = CRCW02010000Z0ED: RES, 0, 5%, 0.05 W, 0201; Manufacturer: Vishay-Dale; CompType: Resistor; Tolerance_%: 5; Power_W: 0.05; Value: 0; U/M: EA; Value_Code: 0000; Value2: 0.05W; EIA_Code: E24; TempCo: ppm/C; SizeArea_mm2: 0.18; SizeX_mm: 0.6; SizeY_mm: 0.3; SizeZ_mm: 0.26; AEC Category: Q200; AEC Qualified: N
R554 R556 = RC0201JR-0751RL: RES, 51, 5%, 0.05 W, 0201; Manufacturer: Yageo America; CompType: Resistor; Value: 51; Value_Code: 51R0; Tolerance_%: 5; Power_W: 0.05; Value2: 0.05W; VDC_V: 25; TempCo: 200 ppm/C; SizeArea_mm2: 0.18; SizeX_mm: 0.6; SizeY_mm: 0.3; SizeZ_mm: 0.26; EIA_Code: E24; U/M: EA; AEC Category: Q200; AEC Qualified: N
T47 = TFMR_5_TC1-1-13M+: RF Transformer; Manufacturer: Mini-Circuits
U7 = LMK04828: LMK04828BISQE/NOPB; Manufacturer: Texas Instruments
U8 = CMP-0077975-1: 1.8V / 2.5V, 10GHz ÷4 Clock Divider with CML Outputs, QFN-16; Manufacturer: ON Semiconductor
U69 = LMK61E2-SIAR: Ultra-Low Jitter Programmable Oscillator with Internal EEPROM, SIA0008B; Alternate PartNumber: LMK61E2-SIAT; Manufacturer: Texas Instruments; SymbolCreator: Altium; CompType: IC; U/M: EA
Y1 = OSC_SM_6_TCO-2100-SERIES_2: Manufacturer: EPSON TOYOCOM; PartNumber: TCO-2111-AA 614.4000MHZ

## Sheet CLOCK MAIN POWER.SchDoc
size 431 x 279 mm; Date: Not shown in title block; ApprovedBy: Not shown in title block; CheckedBy: Not shown in title block; Author: Not shown in title block; CompanyName: Not shown in title block; DrawnBy: Avinash N; Engineer: Not shown in title block; Organization: Not shown in title block; Address1: Not shown in title block; Address2: Not shown in title block; Address3: Not shown in title block; Address4: Not shown in title block; DocumentNumber: 1; Revision: Use project parameter SCH_Rev; SheetNumber: 25; SheetTotal: 32; PageSetup: Record=PageOptions¦CenterHorizontal=True¦CenterVertical=True¦PrintScale=1.00¦XCorrection=1.00¦YCorrection=1.00¦PrintKind=0¦BorderSize=5000000¦LeftOffset=0¦BottomOffset=0¦Orientation=2¦PaperLength=1000¦PaperWidth=1000¦Scale=100¦PaperSource=15¦PrintQuality=600¦MediaType=1¦DitherType=10¦PaperKind=Letter¦PrintScaleMode=1
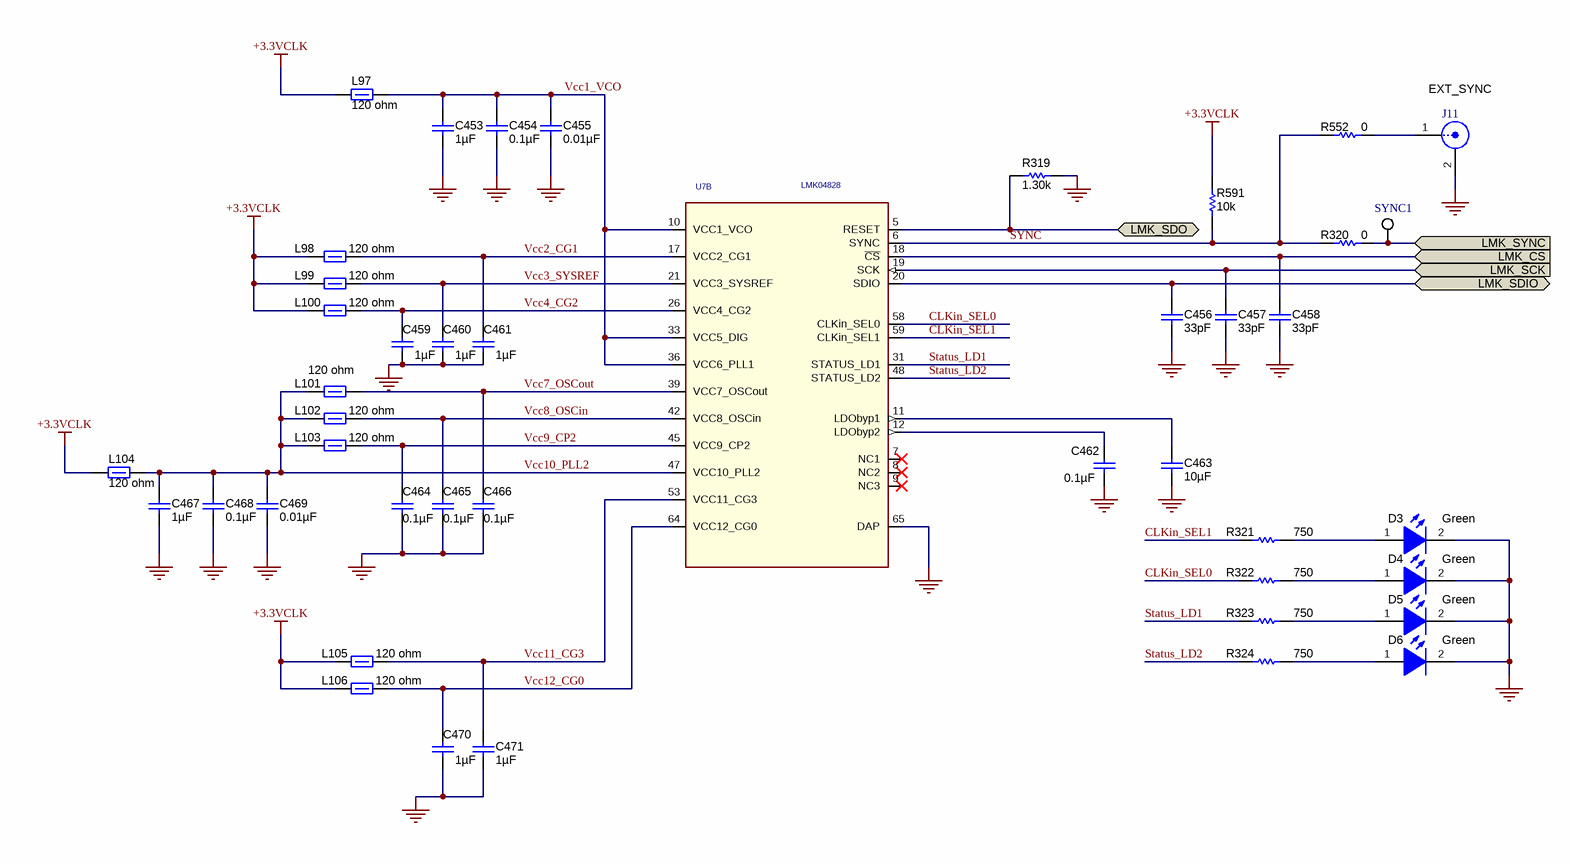
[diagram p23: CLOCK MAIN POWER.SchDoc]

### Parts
C453  ValueDisplayed: 1µF  [0402]  (hidden comment: C1005X7S1A105K050BC)
C454  ValueDisplayed: 0.1µF  [0402]  (hidden comment: GRM155R71C104KA88D)
C455  ValueDisplayed: 0.01µF  [0402]  (hidden comment: GRM155R71E103KA01D)
C456  ValueDisplayed: 33pF  [0603L]  (hidden comment: C0603C330J5GACTU)
C457  ValueDisplayed: 33pF  [0603L]  (hidden comment: C0603C330J5GACTU)
C458  ValueDisplayed: 33pF  [0603L]  (hidden comment: C0603C330J5GACTU)
C459  ValueDisplayed: 1µF  [0402]  (hidden comment: C1005X7S1A105K050BC)
C460  ValueDisplayed: 1µF  [0402]  (hidden comment: C1005X7S1A105K050BC)
C461  ValueDisplayed: 1µF  [0402]  (hidden comment: C1005X7S1A105K050BC)
C462  ValueDisplayed: 0.1µF  [0603]  (hidden comment: C0603C104J3RACTU)
C463  ValueDisplayed: 10µF  [0805_HV]  (hidden comment: C0805C106K8PACTU)
C464  ValueDisplayed: 0.1µF  [0402]  (hidden comment: C1005X7R1E104M050BB)
C465  ValueDisplayed: 0.1µF  [0402]  (hidden comment: C1005X7R1E104M050BB)
C466  ValueDisplayed: 0.1µF  [0402]  (hidden comment: C1005X7R1E104M050BB)
C467  ValueDisplayed: 1µF  [0402]  (hidden comment: C1005X7S1A105K050BC)
C468  ValueDisplayed: 0.1µF  [0402]  (hidden comment: GRM155R71C104KA88D)
C469  ValueDisplayed: 0.01µF  [0402]  (hidden comment: GRM155R71E103KA01D)
C470  ValueDisplayed: 1µF  [0402]  (hidden comment: C1005X7S1A105K050BC)
C471  ValueDisplayed: 1µF  [0402]  (hidden comment: C1005X7S1A105K050BC)
D3  value Green  [LTST-C191_Green]  (hidden comment: LTST-C191TGKT)
D4  value Green  [LTST-C191_Green]  (hidden comment: LTST-C191TGKT)
D5  value Green  [LTST-C191_Green]  (hidden comment: LTST-C191TGKT)
D6  value Green  [LTST-C191_Green]  (hidden comment: LTST-C191TGKT)
J11  EXT_SYNC  [Molex_0853050232]
L97  ValueDisplayed: 120 ohm  [0603]  (hidden comment: BLM18AG121SN1D)
L98  ValueDisplayed: 120 ohm  [0603]  (hidden comment: BLM18AG121SN1D)
L99  ValueDisplayed: 120 ohm  [0603]  (hidden comment: BLM18AG121SN1D)
L100  ValueDisplayed: 120 ohm  [0603]  (hidden comment: BLM18AG121SN1D)
L101  ValueDisplayed: 120 ohm  [0603]  (hidden comment: BLM18AG121SN1D)
L102  ValueDisplayed: 120 ohm  [0603]  (hidden comment: BLM18AG121SN1D)
L103  ValueDisplayed: 120 ohm  [0603]  (hidden comment: BLM18AG121SN1D)
L104  ValueDisplayed: 120 ohm  [0603]  (hidden comment: BLM18AG121SN1D)
L105  ValueDisplayed: 120 ohm  [0603]  (hidden comment: BLM18AG121SN1D)
L106  ValueDisplayed: 120 ohm  [0603]  (hidden comment: BLM18AG121SN1D)
R319  ValueDisplayed: 1.30k  [0402]  (hidden comment: CRCW04021K30FKED)
R320  ValueDisplayed: 0  [0402]  (hidden comment: CRCW04020000Z0ED)
R321  ValueDisplayed: 750  [0603]  (hidden comment: CRCW0603750RFKEA)
R322  ValueDisplayed: 750  [0603]  (hidden comment: CRCW0603750RFKEA)
R323  ValueDisplayed: 750  [0603]  (hidden comment: CRCW0603750RFKEA)
R324  ValueDisplayed: 750  [0603]  (hidden comment: CRCW0603750RFKEA)
R552  ValueDisplayed: 0  [0402]  (hidden comment: CRCW04020000Z0ED)
R591  ValueDisplayed: 10k  [0603]  (hidden comment: CRCW060310K0JNEA)
SYNC1  5002  [Keystone5002]  (value not drawn)
U7  LMK04828  [NKD0064A]  (part B of 2)

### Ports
LMK_CS (in), LMK_SCK (in), LMK_SDIO (bidir), LMK_SDO (bidir), LMK_SYNC (in)

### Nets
+3.3VCLK: L97.1 L98.1 L99.1 L100.1 L104.1 L105.1 L106.1 R591.1
GND: C453.2 C454.2 C455.2 C456.1 C457.1 C458.1 C459.2 C460.2 C461.2 C462.2 C463.2 C464.1 C465.1 C466.1 C467.2 C468.2 C469.2 C470.2 C471.2 D3.2(K) D4.2(K) D5.2(K) D6.2(K) J11.2 R319.2 U7.65(DAP)
CLKin_SEL0: R322.1 U7.58(CLKin_SEL0)
CLKin_SEL1: R321.1 U7.59(CLKin_SEL1)
LMK_CS: C458.2 U7.18(~{CS}) ; port LMK_CS
LMK_SCK: C457.2 U7.19(SCK) ; port LMK_SCK
LMK_SDIO: C456.2 U7.20(SDIO) ; port LMK_SDIO
LMK_SDO: R319.1 U7.5(RESET) ; port LMK_SDO
LMK_SYNC: R320.2 SYNC1.1 ; port LMK_SYNC
Status_LD1: R323.1 U7.31(STATUS_LD1)
Status_LD2: R324.1 U7.48(STATUS_LD2)
SYNC: R320.1 R552.1 R591.2 U7.6(SYNC)
Vcc1_VCO: C453.1 C454.1 C455.1 L97.2 U7.10(VCC1_VCO) U7.33(VCC5_DIG) U7.36(VCC6_PLL1)
Vcc2_CG1: C461.1 L98.2 U7.17(VCC2_CG1)
Vcc3_SYSREF: C460.1 L99.2 U7.21(VCC3_SYSREF)
Vcc4_CG2: C459.1 L100.2 U7.26(VCC4_CG2)
Vcc7_OSCout: C466.2 L101.2 U7.39(VCC7_OSCout)
Vcc8_OSCin: C465.2 L102.2 U7.42(VCC8_OSCin)
Vcc9_CP2: C464.2 L103.2 U7.45(VCC9_CP2)
Vcc10_PLL2: C467.1 C468.1 C469.1 L101.1 L102.1 L103.1 L104.2 U7.47(VCC10_PLL2)
Vcc11_CG3: C471.1 L105.2 U7.53(VCC11_CG3)
Vcc12_CG0: C470.1 L106.2 U7.64(VCC12_CG0)
NetC462_1: C462.1 U7.12(LDObyp2)
NetC463_1: C463.1 U7.11(LDObyp1)
NetD3_1: D3.1(A) R321.2
NetD4_1: D4.1(A) R322.2
NetD5_1: D5.1(A) R323.2
NetD6_1: D6.1(A) R324.2
NetJ11_1: J11.1 R552.2

Not connected (* = marked no-connect by the designer): U7 7(NC1)* 8(NC2)* 9(NC3)*

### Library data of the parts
C453 C459-C461 C467 C470 C471 = C1005X7S1A105K050BC: CAP, CERM, 1 µF, 10 V, +/- 10%, X7S, 0402; Manufacturer: TDK; Polarized: N; CompType: Capacitor; Value: 1uF; U/M: EA; Cap_F: 0.000001; Tolerance_%: 10; ESR_ohm: 0.011416; Value1: 0.011416 ohm; Value2: 10V; IRMS_A: 1.483; TaMin_C: -55; TaMax_C: 125; SizeArea_mm2: 0.5; SizeAreaWB_mm2: 3; SizeX_mm: 1; SizeZ_mm: 0.6; AEC Category: Q200
C454 C468 = GRM155R71C104KA88D: CAP, CERM, 0.1 µF, 16 V, +/- 10%, X7R, 0402; Manufacturer: MuRata; Polarized: N; CompType: Capacitor; Value: 0.1uF; U/M: EA; Cap_F: 0.0000001; Tolerance_%: 10; Value1: Unknown; VDC_V: 16; Value2: 16V; TaMin_C: -55; TaMax_C: 125; SizeArea_mm2: 0.5; SizeAreaWB_mm2: 3; SizeX_mm: 1; SizeZ_mm: 0.6; AEC Category: Q200
C455 C469 = GRM155R71E103KA01D: as C702 on sheet CLOCK MAIN SHEET
C456-C458 = C0603C330J5GACTU: CAP, CERM, 33pF, 50V, +/-5%, C0G/NP0, 0603; Manufacturer: Kemet; Cap_Case: 0603; Polarized: N; TaMax_C: 125; TaMin_C: -55; Tolerance_%: 5; VDC_V: 50; Cap_F: 0.000000000033; CompType: Capacitor; U/M: EA; Value1: Unknown
C462 = C0603C104J3RACTU: CAP, CERM, 0.1uF, 25V, +/-5%, X7R, 0603; Manufacturer: Kemet; Polarized: N; TaMax_C: 125; TaMin_C: -55; Tolerance_%: 5; VDC_V: 25; Cap_F: 0.0000001; CompType: Capacitor; Value1: Unknown; U/M: EA
C463 = C0805C106K8PACTU: CAP, CERM, 10uF, 10V, +/-10%, X5R, 0805; Manufacturer: Kemet; Cap_Case: 0805; ESR_Ohm: 0.003; IRMS_A: 11.43; Polarized: N; TaMax_C: 85; TaMin_C: -55; Tolerance_%: 10; Cap_F: 0.00001; CompType: Capacitor; Value1: 0.003 ohm; U/M: EA
C464-C466 = C1005X7R1E104M050BB: as C225 on sheet CLOCK MAIN SHEET
D3-D6 = LTST-C191TGKT: LED, Green, SMD; Manufacturer: Lite-On; Type: InGaN; Vf_V: 3.2; Value2: 3.2V; Io_A: 0.02; Value1: W; U/M: EA
J11 = CMP-0077224-1: as J12 on sheet CLOCK MAIN SHEET
L97-L106 = BLM18AG121SN1D: Ferrite Bead, 120 ohm @ 100 MHz, 0.5 A, 0603; Manufacturer: MuRata; Value: 120 ohm; Imax_A: 0.5; DCR_ohm: 0.18; Value1: 0.18 ohm; Value2: 0.5A; SizeAreaWB_mm2: 4.68; SizeArea_mm2: 1.28; SizeX_mm: 1.6; SizeY_mm: 0.8; SizeZ_mm: 1; ZTyp@100MHz_Ohm: 120
R319 = CRCW04021K30FKED: RES, 1.30 k, 1%, 0.063 W, 0402; Manufacturer: Vishay-Dale; CompType: Resistor; Value: 1.30k; Res_ohm: 1300; Value_Code: 1k30; Tolerance_%: 1; Power_W: 0.063; Value2: 0.063W; VDC_V: 50; TempCo: 100 ppm/C; SizeArea_mm2: 0.5; SizeZ_mm: 0.6; EIA_Code: E96; U/M: EA; AEC Category: Q200
R320 R552 = CRCW04020000Z0ED: RES, 0, 5%, 0.063 W, 0402; Manufacturer: Vishay-Dale; CompType: Resistor; Value: 0; Value_Code: 0000; Tolerance_%: 5; Power_W: 0.063; Value2: 0.063W; VDC_V: 50; TempCo: 200 ppm/C; SizeArea_mm2: 0.5; SizeX_mm: 1; SizeZ_mm: 0.6; EIA_Code: E24; U/M: EA; AEC Category: Q200
R321-R324 = CRCW0603750RFKEA: RES, 750, 1%, 0.1 W, 0603; Manufacturer: Vishay-Dale; CompType: Resistor; Value: 750; Value_Code: 750R; Tolerance_%: 1; Power_W: 0.1; Value2: 0.1W; VDC_V: 75; TempCo: 100 ppm/C; SizeArea_mm2: 1.28; SizeX_mm: 1.6; SizeY_mm: 0.8; EIA_Code: E96; U/M: EA; AEC Category: Q200
R591 = CRCW060310K0JNEA: RES, 10 k, 5%, 0.1 W, 0603; Manufacturer: Vishay-Dale; CompType: Resistor; Value: 10k; Res_ohm: 10000; Value_Code: 10k0; Tolerance_%: 5; Power_W: 0.1; Value2: 0.1W; VDC_V: 75; TempCo: 200 ppm/C; SizeArea_mm2: 1.28; SizeX_mm: 1.6; SizeY_mm: 0.8; SizeZ_mm: 1; EIA_Code: E24; U/M: EA; AEC Category: Q200
SYNC1 = 5002: Test Point, Miniature, White, TH; Manufacturer: Keystone; CompType: Test Point Loop; ContactFinish: Silver; Green_Lifecycle: Active; Green_REACh: Passed
U7 = LMK04828: as U7 on sheet CLOCK MAIN SHEET

## Sheet CLOCK BUFFER.SchDoc: LMK00304_Buffer
size 431 x 279 mm; Date: Not shown in title block; ApprovedBy: Not shown in title block; CheckedBy: Not shown in title block; Author: Not shown in title block; CompanyName: Not shown in title block; DrawnBy: Avinash N; Engineer: Not shown in title block; Organization: Not shown in title block; Address1: Not shown in title block; Address2: Not shown in title block; Address3: Not shown in title block; Address4: Not shown in title block; DocumentNumber: 1; Revision: Use project parameter SCH_Rev; SheetNumber: 26; SheetTotal: 32; PageSetup: Record=PageOptions¦CenterHorizontal=True¦CenterVertical=True¦PrintScale=1.00¦XCorrection=1.00¦YCorrection=1.00¦PrintKind=0¦BorderSize=5000000¦LeftOffset=0¦BottomOffset=0¦Orientation=2¦PaperLength=1000¦PaperWidth=1000¦Scale=100¦PaperSource=15¦PrintQuality=600¦MediaType=1¦DitherType=10¦PaperKind=Letter¦PrintScaleMode=1
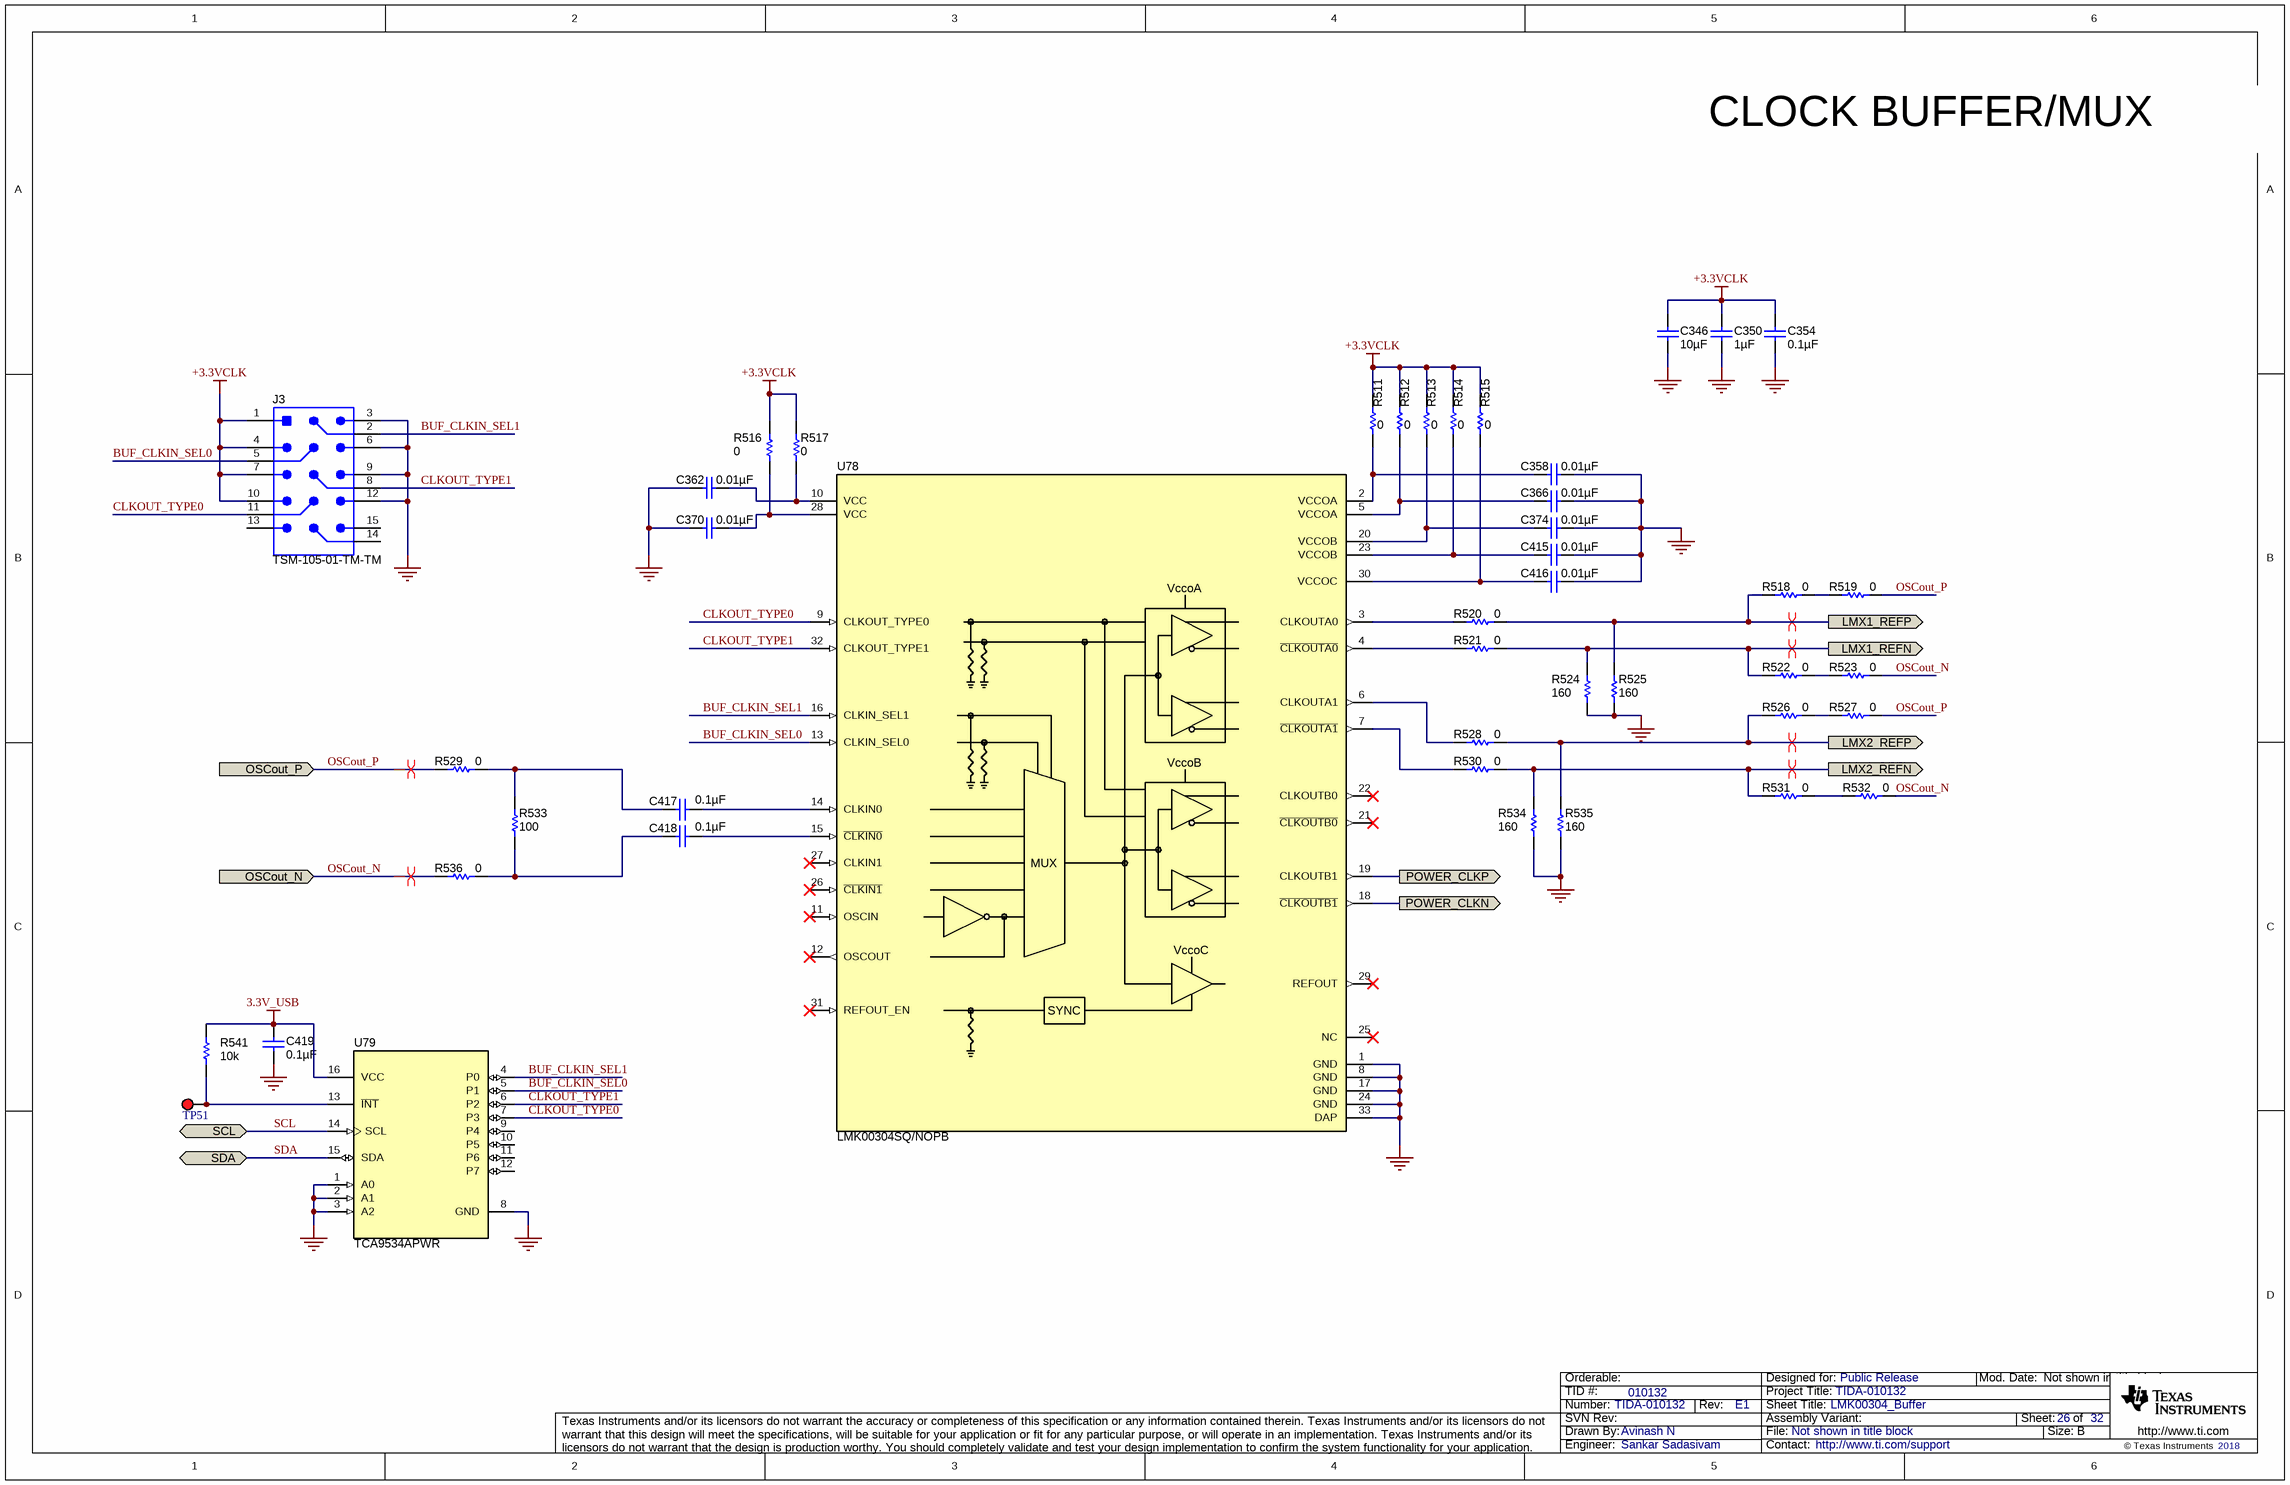
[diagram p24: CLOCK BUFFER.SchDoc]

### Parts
C346  ValueDisplayed: 10µF  [0603]  (hidden comment: EMK107BBJ106MA-T)
C350  ValueDisplayed: 1µF  [0402]  (hidden comment: C1005X7S1A105K050BC)
C354  ValueDisplayed: 0.1µF  [0402]  (hidden comment: GRM155R71C104KA88D)
C358  ValueDisplayed: 0.01µF  [0402]  (hidden comment: GRM155R71E103KA01D)
C362  ValueDisplayed: 0.01µF  [0402]  (hidden comment: GRM155R71E103KA01D)
C366  ValueDisplayed: 0.01µF  [0402]  (hidden comment: GRM155R71E103KA01D)
C370  ValueDisplayed: 0.01µF  [0402]  (hidden comment: GRM155R71E103KA01D)
C374  ValueDisplayed: 0.01µF  [0402]  (hidden comment: GRM155R71E103KA01D)
C415  ValueDisplayed: 0.01µF  [0402]  (hidden comment: GRM155R71E103KA01D)
C416  ValueDisplayed: 0.01µF  [0402]  (hidden comment: GRM155R71E103KA01D)
C417  ValueDisplayed: 0.1µF  [0402]  (hidden comment: C1005X7R1E104M050BB)
C418  ValueDisplayed: 0.1µF  [0402]  (hidden comment: C1005X7R1E104M050BB)
C419  ValueDisplayed: 0.1µF  [0603]  (hidden comment: C0603C104J3RACTU)
J3  TSM-105-01-TM-TM  [Samtec_TSM-105-01-xx-TM]
R511  ValueDisplayed: 0  [0402]  (hidden comment: CRCW04020000Z0ED)
R512  ValueDisplayed: 0  [0402]  (hidden comment: CRCW04020000Z0ED)
R513  ValueDisplayed: 0  [0402]  (hidden comment: CRCW04020000Z0ED)
R514  ValueDisplayed: 0  [0402]  (hidden comment: CRCW04020000Z0ED)
R515  ValueDisplayed: 0  [0402]  (hidden comment: CRCW04020000Z0ED)
R516  ValueDisplayed: 0  [0402]  (hidden comment: CRCW04020000Z0ED)
R517  ValueDisplayed: 0  [0402]  (hidden comment: CRCW04020000Z0ED)
R518  ValueDisplayed: 0  [0402]  (hidden comment: CRCW04020000Z0ED)
R519  ValueDisplayed: 0  [0402]  (hidden comment: CRCW04020000Z0ED)
R520  ValueDisplayed: 0  [0402]  (hidden comment: CRCW04020000Z0ED)
R521  ValueDisplayed: 0  [0402]  (hidden comment: CRCW04020000Z0ED)
R522  ValueDisplayed: 0  [0402]  (hidden comment: CRCW04020000Z0ED)
R523  ValueDisplayed: 0  [0402]  (hidden comment: CRCW04020000Z0ED)
R524  ValueDisplayed: 160  [0402]  (hidden comment: CRCW0402160RJNED)
R525  ValueDisplayed: 160  [0402]  (hidden comment: CRCW0402160RJNED)
R526  ValueDisplayed: 0  [0402]  (hidden comment: CRCW04020000Z0ED)
R527  ValueDisplayed: 0  [0402]  (hidden comment: CRCW04020000Z0ED)
R528  ValueDisplayed: 0  [0402]  (hidden comment: CRCW04020000Z0ED)
R529  ValueDisplayed: 0  [0402]  (hidden comment: CRCW04020000Z0ED)
R530  ValueDisplayed: 0  [0402]  (hidden comment: CRCW04020000Z0ED)
R531  ValueDisplayed: 0  [0402]  (hidden comment: CRCW04020000Z0ED)
R532  ValueDisplayed: 0  [0402]  (hidden comment: CRCW04020000Z0ED)
R533  ValueDisplayed: 100  [0402]  (hidden comment: CRCW0402100RFKED)
R534  ValueDisplayed: 160  [0402]  (hidden comment: CRCW0402160RJNED)
R535  ValueDisplayed: 160  [0402]  (hidden comment: CRCW0402160RJNED)
R536  ValueDisplayed: 0  [0402]  (hidden comment: CRCW04020000Z0ED)
R541  ValueDisplayed: 10k  [0603]  (hidden comment: CRCW060310K0JNEA)
TP51  5000  [Keystone5000]  (value not drawn)
U78  LMK00304SQ/NOPB  [RTV0032A]
U79  TCA9534APWR  [PW0016A_N]

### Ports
LMX1_REFN (out), LMX1_REFP (out), LMX2_REFN (out), LMX2_REFP (out), OSCout_N (in), OSCout_P (in), POWER_CLKN (out), POWER_CLKP (out), SCL (bidir), SDA (bidir)

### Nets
3.3V_USB: C419.2 R541.2 U79.16(VCC)
+3.3VCLK: C346.1 C350.1 C354.1 J3.1 J3.4 J3.7 J3.10 R511.2 R512.2 R513.2 R514.2 R515.2 R516.2 R517.2
GND: C346.2 C350.2 C354.2 C358.2 C362.1 C366.2 C370.1 C374.2 C415.2 C416.2 C419.1 J3.3 J3.6 J3.9 J3.12 R524.1 R525.1 R534.1 R535.1 U78.1(GND) U78.8(GND) U78.17(GND) U78.24(GND) U78.33(DAP) U79.1(A0) U79.2(A1) U79.3(A2) U79.8(GND)
BUF_CLKIN_SEL0: J3.5 U78.13(CLKIN_SEL0) U79.5(P1)
BUF_CLKIN_SEL1: J3.2 U78.16(CLKIN_SEL1) U79.4(P0)
CLKOUT_TYPE0: J3.11 U78.9(CLKOUT_TYPE0) U79.7(P3)
CLKOUT_TYPE1: J3.8 U78.32(CLKOUT_TYPE1) U79.6(P2)
LMX1_REFN: R521.2 R522.1 R524.2 ; port LMX1_REFN
LMX1_REFP: R518.1 R520.2 R525.2 ; port LMX1_REFP
LMX2_REFN: R530.2 R531.1 R534.2 ; port LMX2_REFN
LMX2_REFP: R526.1 R528.2 R535.2 ; port LMX2_REFP
OSCout_N: R523.2 R532.2 R536.1 ; port OSCout_N
OSCout_P: R519.2 R527.2 R529.1 ; port OSCout_P
POWER_CLKN: U78.18(~{CLKOUTB1}) ; port POWER_CLKN
POWER_CLKP: U78.19(CLKOUTB1) ; port POWER_CLKP
SCL: U79.14(SCL) ; port SCL
SDA: U79.15(SDA) ; port SDA
NetC358_1: C358.1 R511.1 U78.2(VCCOA)
NetC362_2: C362.2 R517.1 U78.10(VCC)
NetC366_1: C366.1 R512.1 U78.5(VCCOA)
NetC370_2: C370.2 R516.1 U78.28(VCC)
NetC374_1: C374.1 R513.1 U78.20(VCCOB)
NetC415_1: C415.1 R514.1 U78.23(VCCOB)
NetC416_1: C416.1 R515.1 U78.30(VCCOC)
NetC417_1: C417.1 R529.2 R533.2
NetC417_2: C417.2 U78.14(CLKIN0)
NetC418_1: C418.1 R533.1 R536.2
NetC418_2: C418.2 U78.15(~{CLKIN0})
NetR518_2: R518.2 R519.1
NetR520_1: R520.1 U78.3(CLKOUTA0)
NetR521_1: R521.1 U78.4(~{CLKOUTA0})
NetR522_2: R522.2 R523.1
NetR526_2: R526.2 R527.1
NetR528_1: R528.1 U78.6(CLKOUTA1)
NetR530_1: R530.1 U78.7(~{CLKOUTA1})
NetR531_2: R531.2 R532.1
NetR541_1: R541.1 TP51.1 U79.13(~{INT})

Not connected (* = marked no-connect by the designer): J3 13 14 15; U78 11(OSCIN)* 12(OSCOUT)* 21(~{CLKOUTB0})* 22(CLKOUTB0)* 25(NC)* 26(~{CLKIN1})* 27(CLKIN1)* 29(REFOUT)* 31(REFOUT_EN)*; U79 9(P4) 10(P5) 11(P6) 12(P7)

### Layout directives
differential pair: LMX1_REFN, LMX1_REFP, LMX2_REFN, LMX2_REFP, OSCout_N, OSCout_P

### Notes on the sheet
- CLOCK BUFFER/MUX

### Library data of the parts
C346 = EMK107BBJ106MA-T: CAP, CERM, 10 µF, 16 V, +/- 20%, X5R, 0603; Manufacturer: Taiyo Yuden; Polarized: N; CompType: Capacitor; Value: 10uF; U/M: EA; Cap_F: 0.00001; Tolerance_%: 20; Value1: Unknown; VDC_V: 16; Value2: 16V; TaMin_C: -55; TaMax_C: 85; SizeArea_mm2: 1.28; SizeAreaWB_mm2: 4.68; SizeX_mm: 1.6; SizeY_mm: 0.8; SizeZ_mm: 1; AEC Category: Q200
C350 = C1005X7S1A105K050BC: as C453 on sheet CLOCK MAIN POWER
C354 = GRM155R71C104KA88D: as C454 on sheet CLOCK MAIN POWER
C358 C362 C366 C370 C374 C415 C416 = GRM155R71E103KA01D: as C702 on sheet CLOCK MAIN SHEET
C417 C418 = C1005X7R1E104M050BB: as C225 on sheet CLOCK MAIN SHEET
C419 = C0603C104J3RACTU: as C462 on sheet CLOCK MAIN POWER
J3 = CMP-0084557-1: Header, 2.54mm, 5x3, Tin, SMT; Manufacturer: Samtec; Voltage_V: 475V; Pitch_mm: 2.54; Row_Count: 3; Gender: Male; Shrouded: N; Cert_UL: Y; Current_A: 5.4A
R511-R523 R526-R532 R536 = CRCW04020000Z0ED: as R320 on sheet CLOCK MAIN POWER
R524 R525 R534 R535 = CRCW0402160RJNED: RES, 160, 5%, 0.063 W, 0402; Manufacturer: Vishay-Dale; CompType: Resistor; Value: 160; Value_Code: 160R; Tolerance_%: 5; Power_W: 0.063; Value2: 0.063W; VDC_V: 50; TempCo: 200 ppm/C; SizeArea_mm2: 0.5; SizeX_mm: 1; SizeZ_mm: 0.6; EIA_Code: E24; U/M: EA; AEC Category: Q200
R533 = CRCW0402100RFKED: RES, 100, 1%, 0.063 W, 0402; Manufacturer: Vishay-Dale; CompType: Resistor; Value: 100; Value_Code: 100R; Tolerance_%: 1; Power_W: 0.063; Value2: 0.063W; VDC_V: 50; TempCo: 100 ppm/C; SizeArea_mm2: 0.5; SizeZ_mm: 0.6; EIA_Code: E96; U/M: EA; AEC Category: Q200
R541 = CRCW060310K0JNEA: as R591 on sheet CLOCK MAIN POWER
TP51 = 5000: Test Point, Miniature, Red, TH; Manufacturer: Keystone; CompType: Test Point Loop; ContactFinish: Silver
U78 = LMK00304SQ/NOPB: 3.1-GHz Differential Clock Buffer/Level Translator, RTV0032A (WQFN-32); Manufacturer: Texas Instruments; SymbolCreator: a0411947; SizeArea_mm2: 25; SizeAreaWB_mm2: 49; SizeX_mm: 5; SizeZ_mm: 0.8; CompType: IC; U/M: EA
U79 = TCA9534APWR: Remote 8-Bit I2C and Low-Power I/O Expander With Interrupt Output and Configuration Registers, PW0016A (TSSOP-16); Manufacturer: Texas Instruments; SymbolCreator: Altium; SizeArea_mm2: 32; SizeAreaWB_mm2: 58.8; SizeX_mm: 6.4; SizeY_mm: 5; SizeZ_mm: 1.2; CompType: IC; U/M: EA

## Sheet POWER TREE.SchDoc
size 431 x 279 mm; Date: Not shown in title block; ApprovedBy: Not shown in title block; CheckedBy: Not shown in title block; Author: Not shown in title block; CompanyName: Not shown in title block; DrawnBy: Avinash N; Engineer: Not shown in title block; Organization: Not shown in title block; Address1: Not shown in title block; Address2: Not shown in title block; Address3: Not shown in title block; Address4: Not shown in title block; DocumentNumber: 1; Revision: Use project parameter SCH_Rev; SheetNumber: 29; SheetTotal: 32; PageSetup: Record=PageOptions¦CenterHorizontal=True¦CenterVertical=True¦PrintScale=1.00¦XCorrection=1.00¦YCorrection=1.00¦PrintKind=0¦BorderSize=5000000¦LeftOffset=0¦BottomOffset=0¦Orientation=2¦PaperLength=1000¦PaperWidth=1000¦Scale=100¦PaperSource=15¦PrintQuality=600¦MediaType=1¦DitherType=10¦PaperKind=Letter¦PrintScaleMode=1
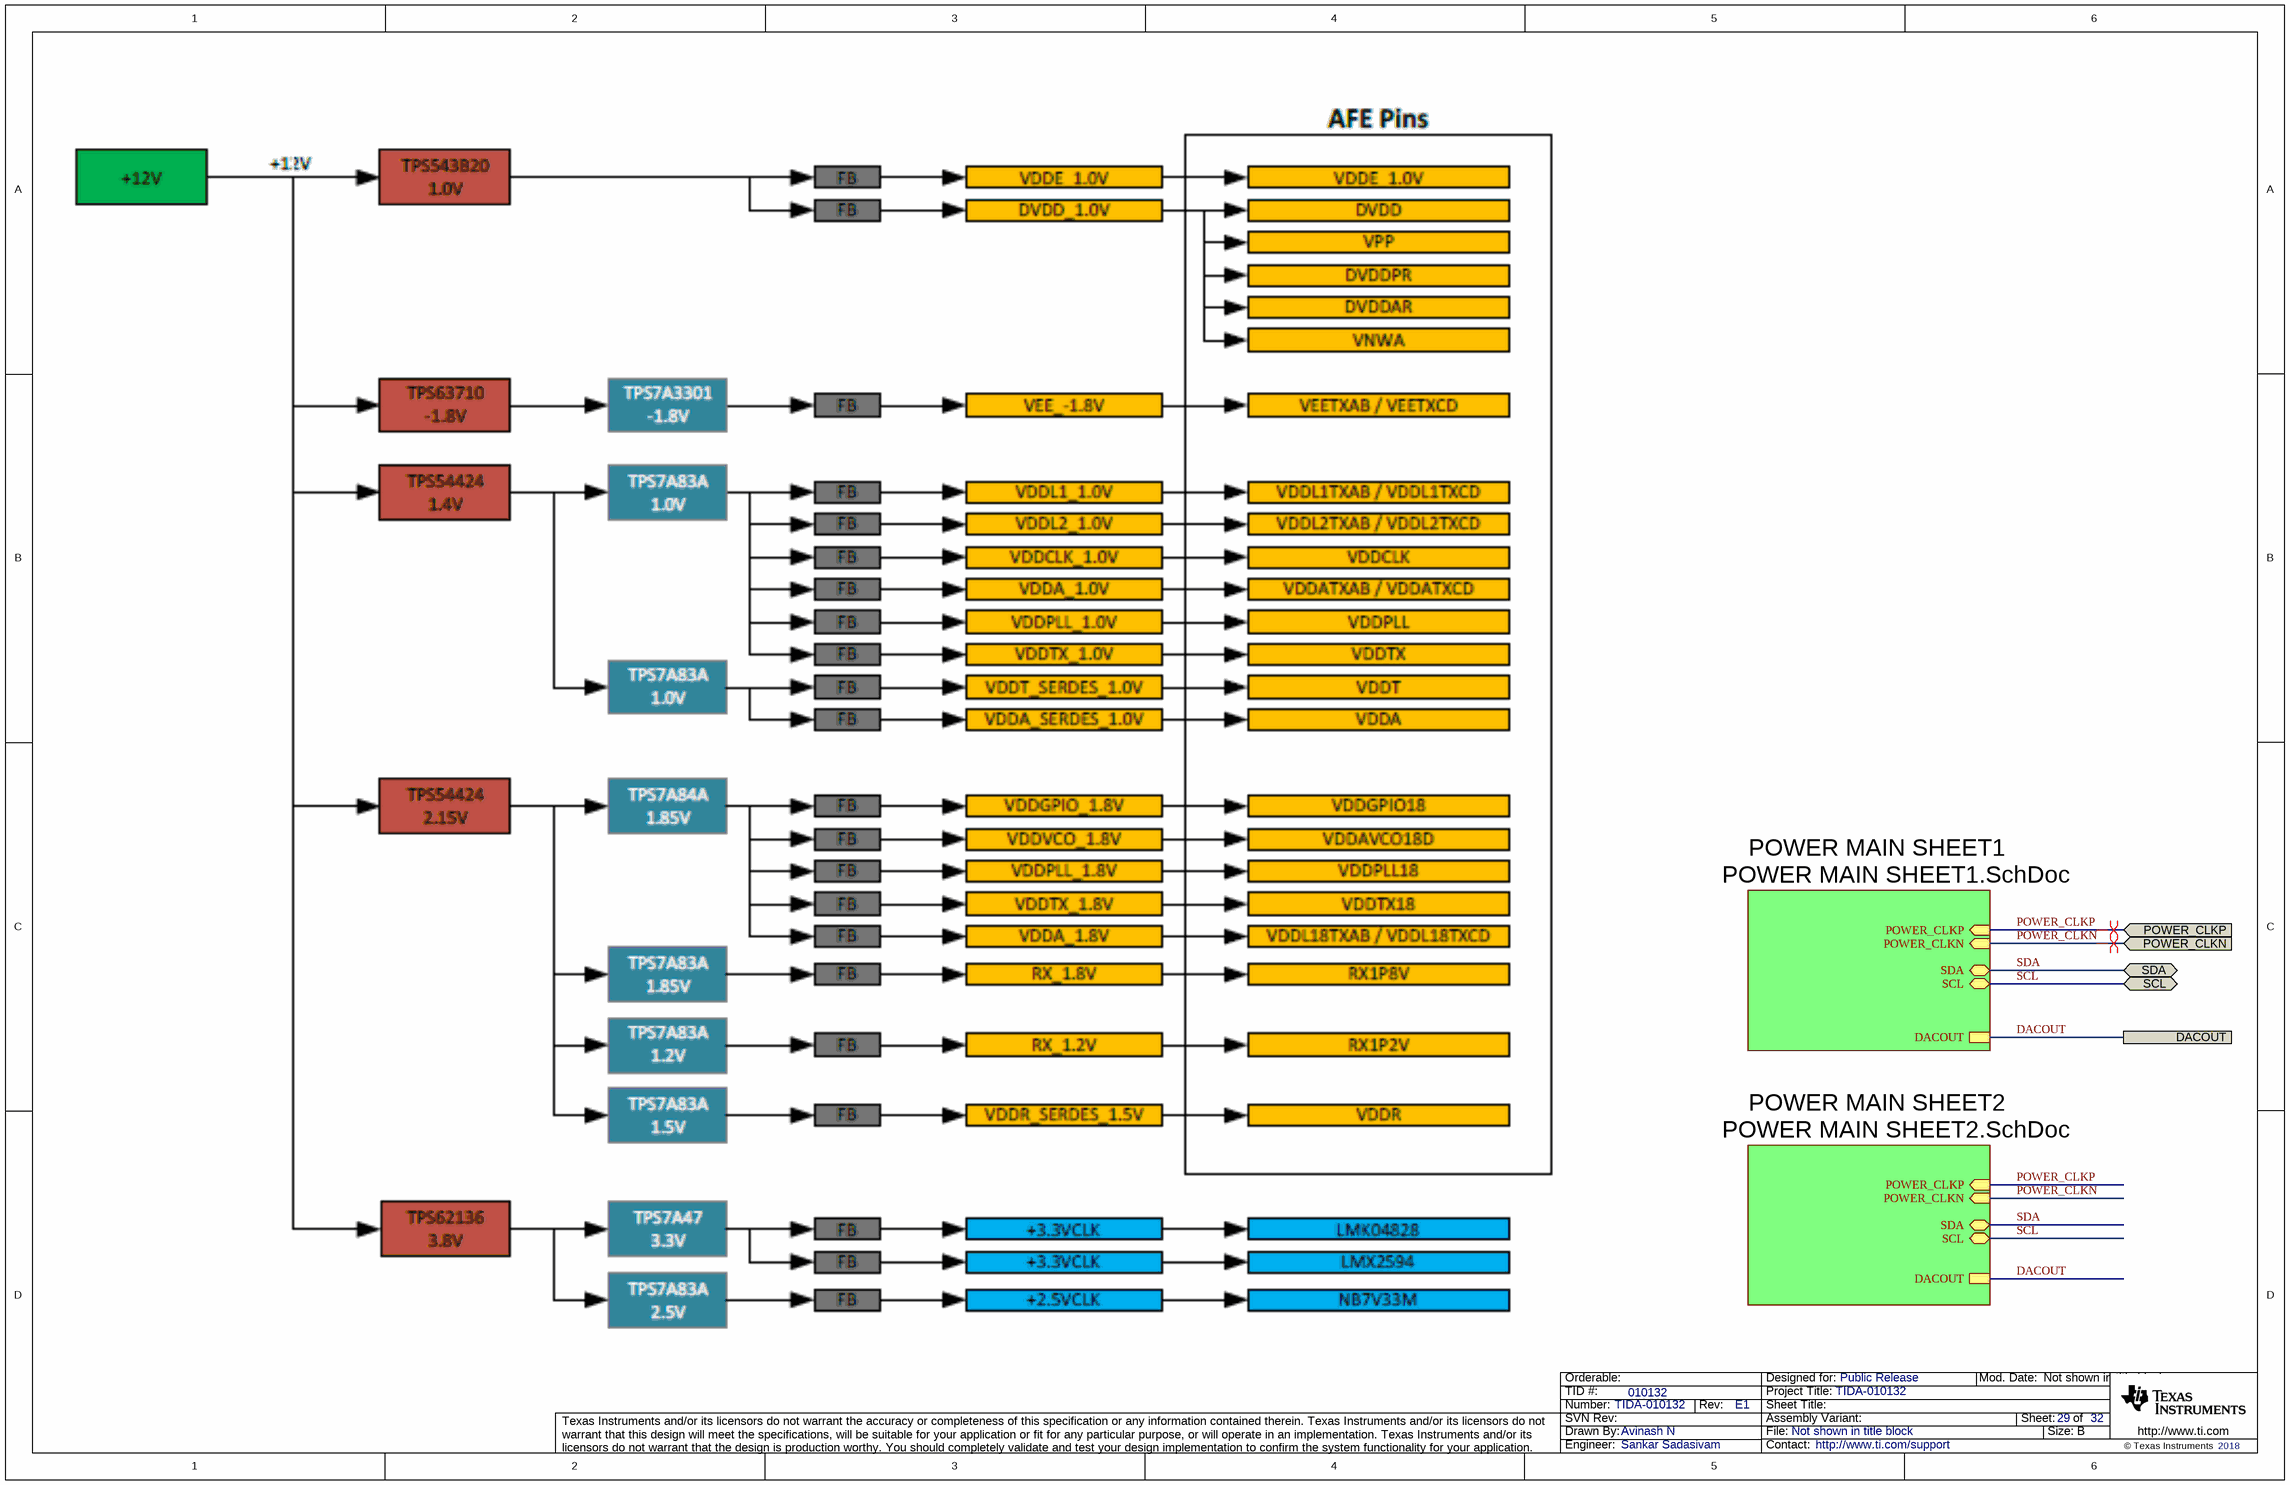
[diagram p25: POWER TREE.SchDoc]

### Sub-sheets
POWER MAIN SHEET1 = POWER MAIN SHEET1.SchDoc: POWER_CLKN (in), DACOUT, POWER_CLKP (in), SDA (bidir), SCL (bidir)
POWER MAIN SHEET2 = POWER MAIN SHEET2.SchDoc: DACOUT, POWER_CLKN (in), POWER_CLKP (in), SDA (bidir), SCL (bidir)

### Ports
DACOUT, POWER_CLKN (in), POWER_CLKP (in), SCL (bidir), SDA (bidir)

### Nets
DACOUT: port DACOUT, sheet POWER MAIN SHEET1/DACOUT, sheet POWER MAIN SHEET2/DACOUT
POWER_CLKN: port POWER_CLKN, sheet POWER MAIN SHEET1/POWER_CLKN, sheet POWER MAIN SHEET2/POWER_CLKN
POWER_CLKP: port POWER_CLKP, sheet POWER MAIN SHEET1/POWER_CLKP, sheet POWER MAIN SHEET2/POWER_CLKP
SCL: port SCL, sheet POWER MAIN SHEET1/SCL, sheet POWER MAIN SHEET2/SCL
SDA: port SDA, sheet POWER MAIN SHEET1/SDA, sheet POWER MAIN SHEET2/SDA

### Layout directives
differential pair: POWER_CLKN, POWER_CLKP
